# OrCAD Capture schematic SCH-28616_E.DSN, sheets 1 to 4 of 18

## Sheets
1 X-02 IOMUX: title: MCIMX6UL-BB; rev: E; company: Freescale Semiconductor; note: SCH-28616 PDF: SPF-28616; note: 6501 William Cannon Drive West; note: Austin, TX 78735-8598
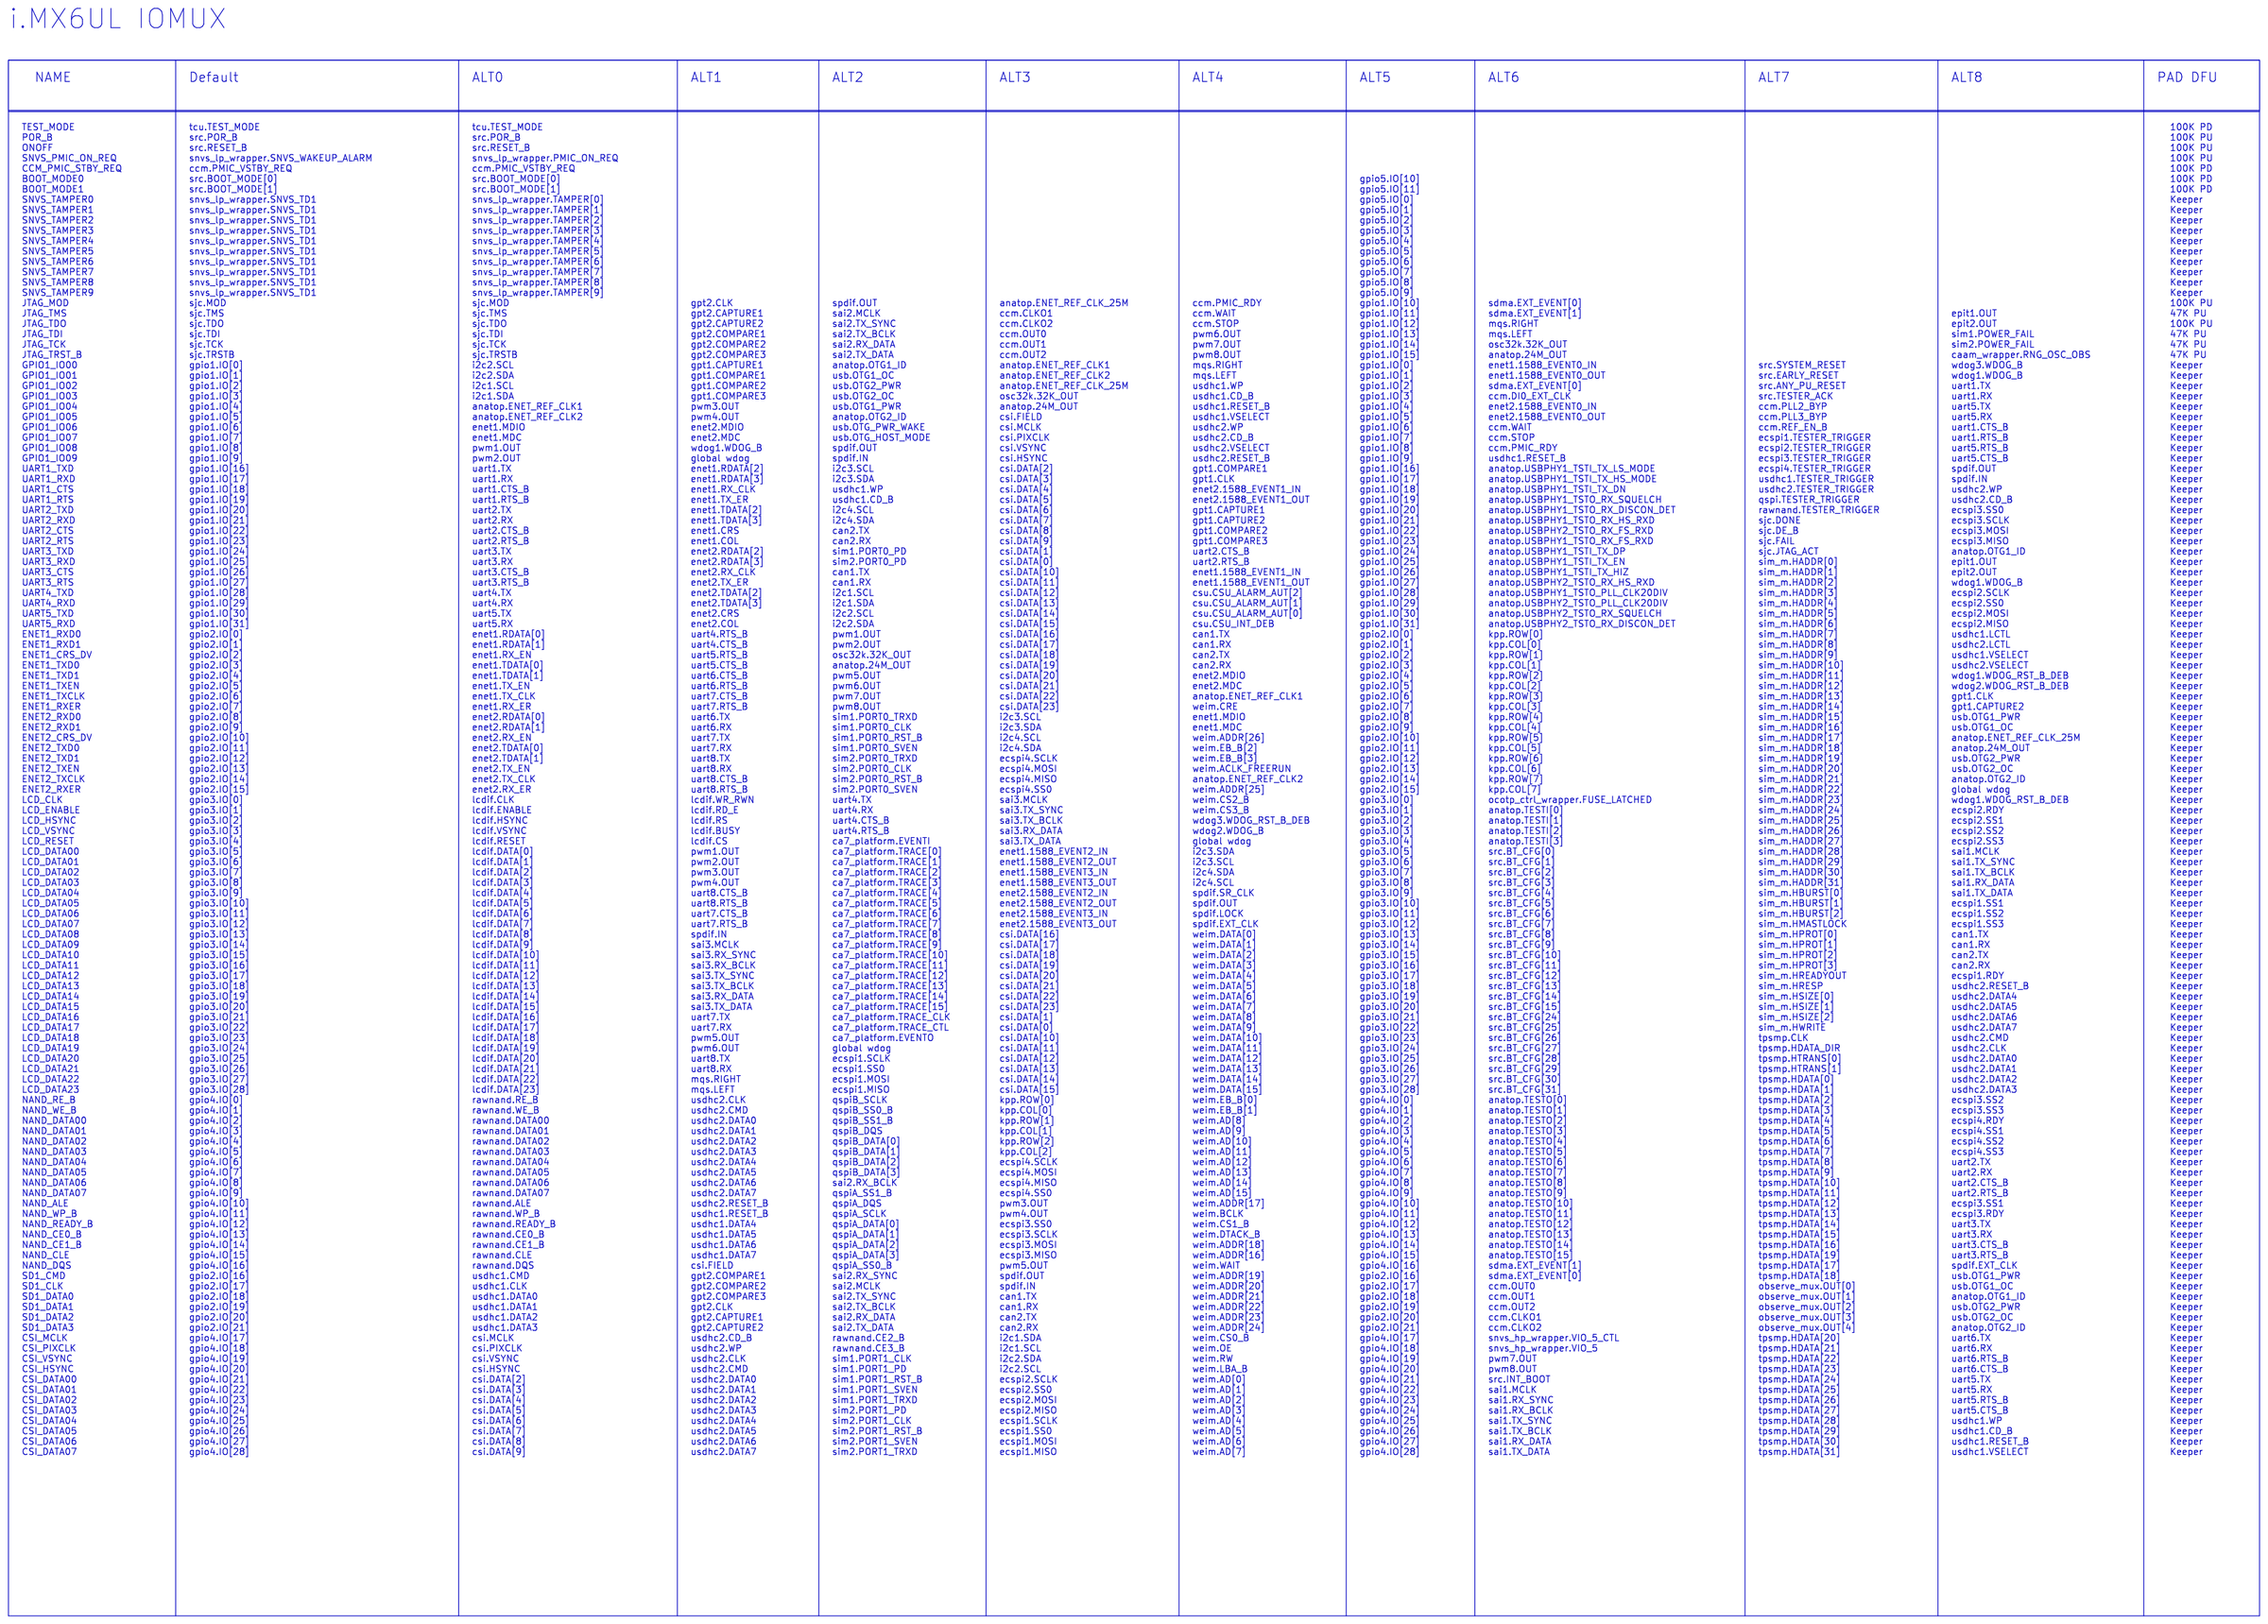
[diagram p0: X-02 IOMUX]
2 X-01 NOTE
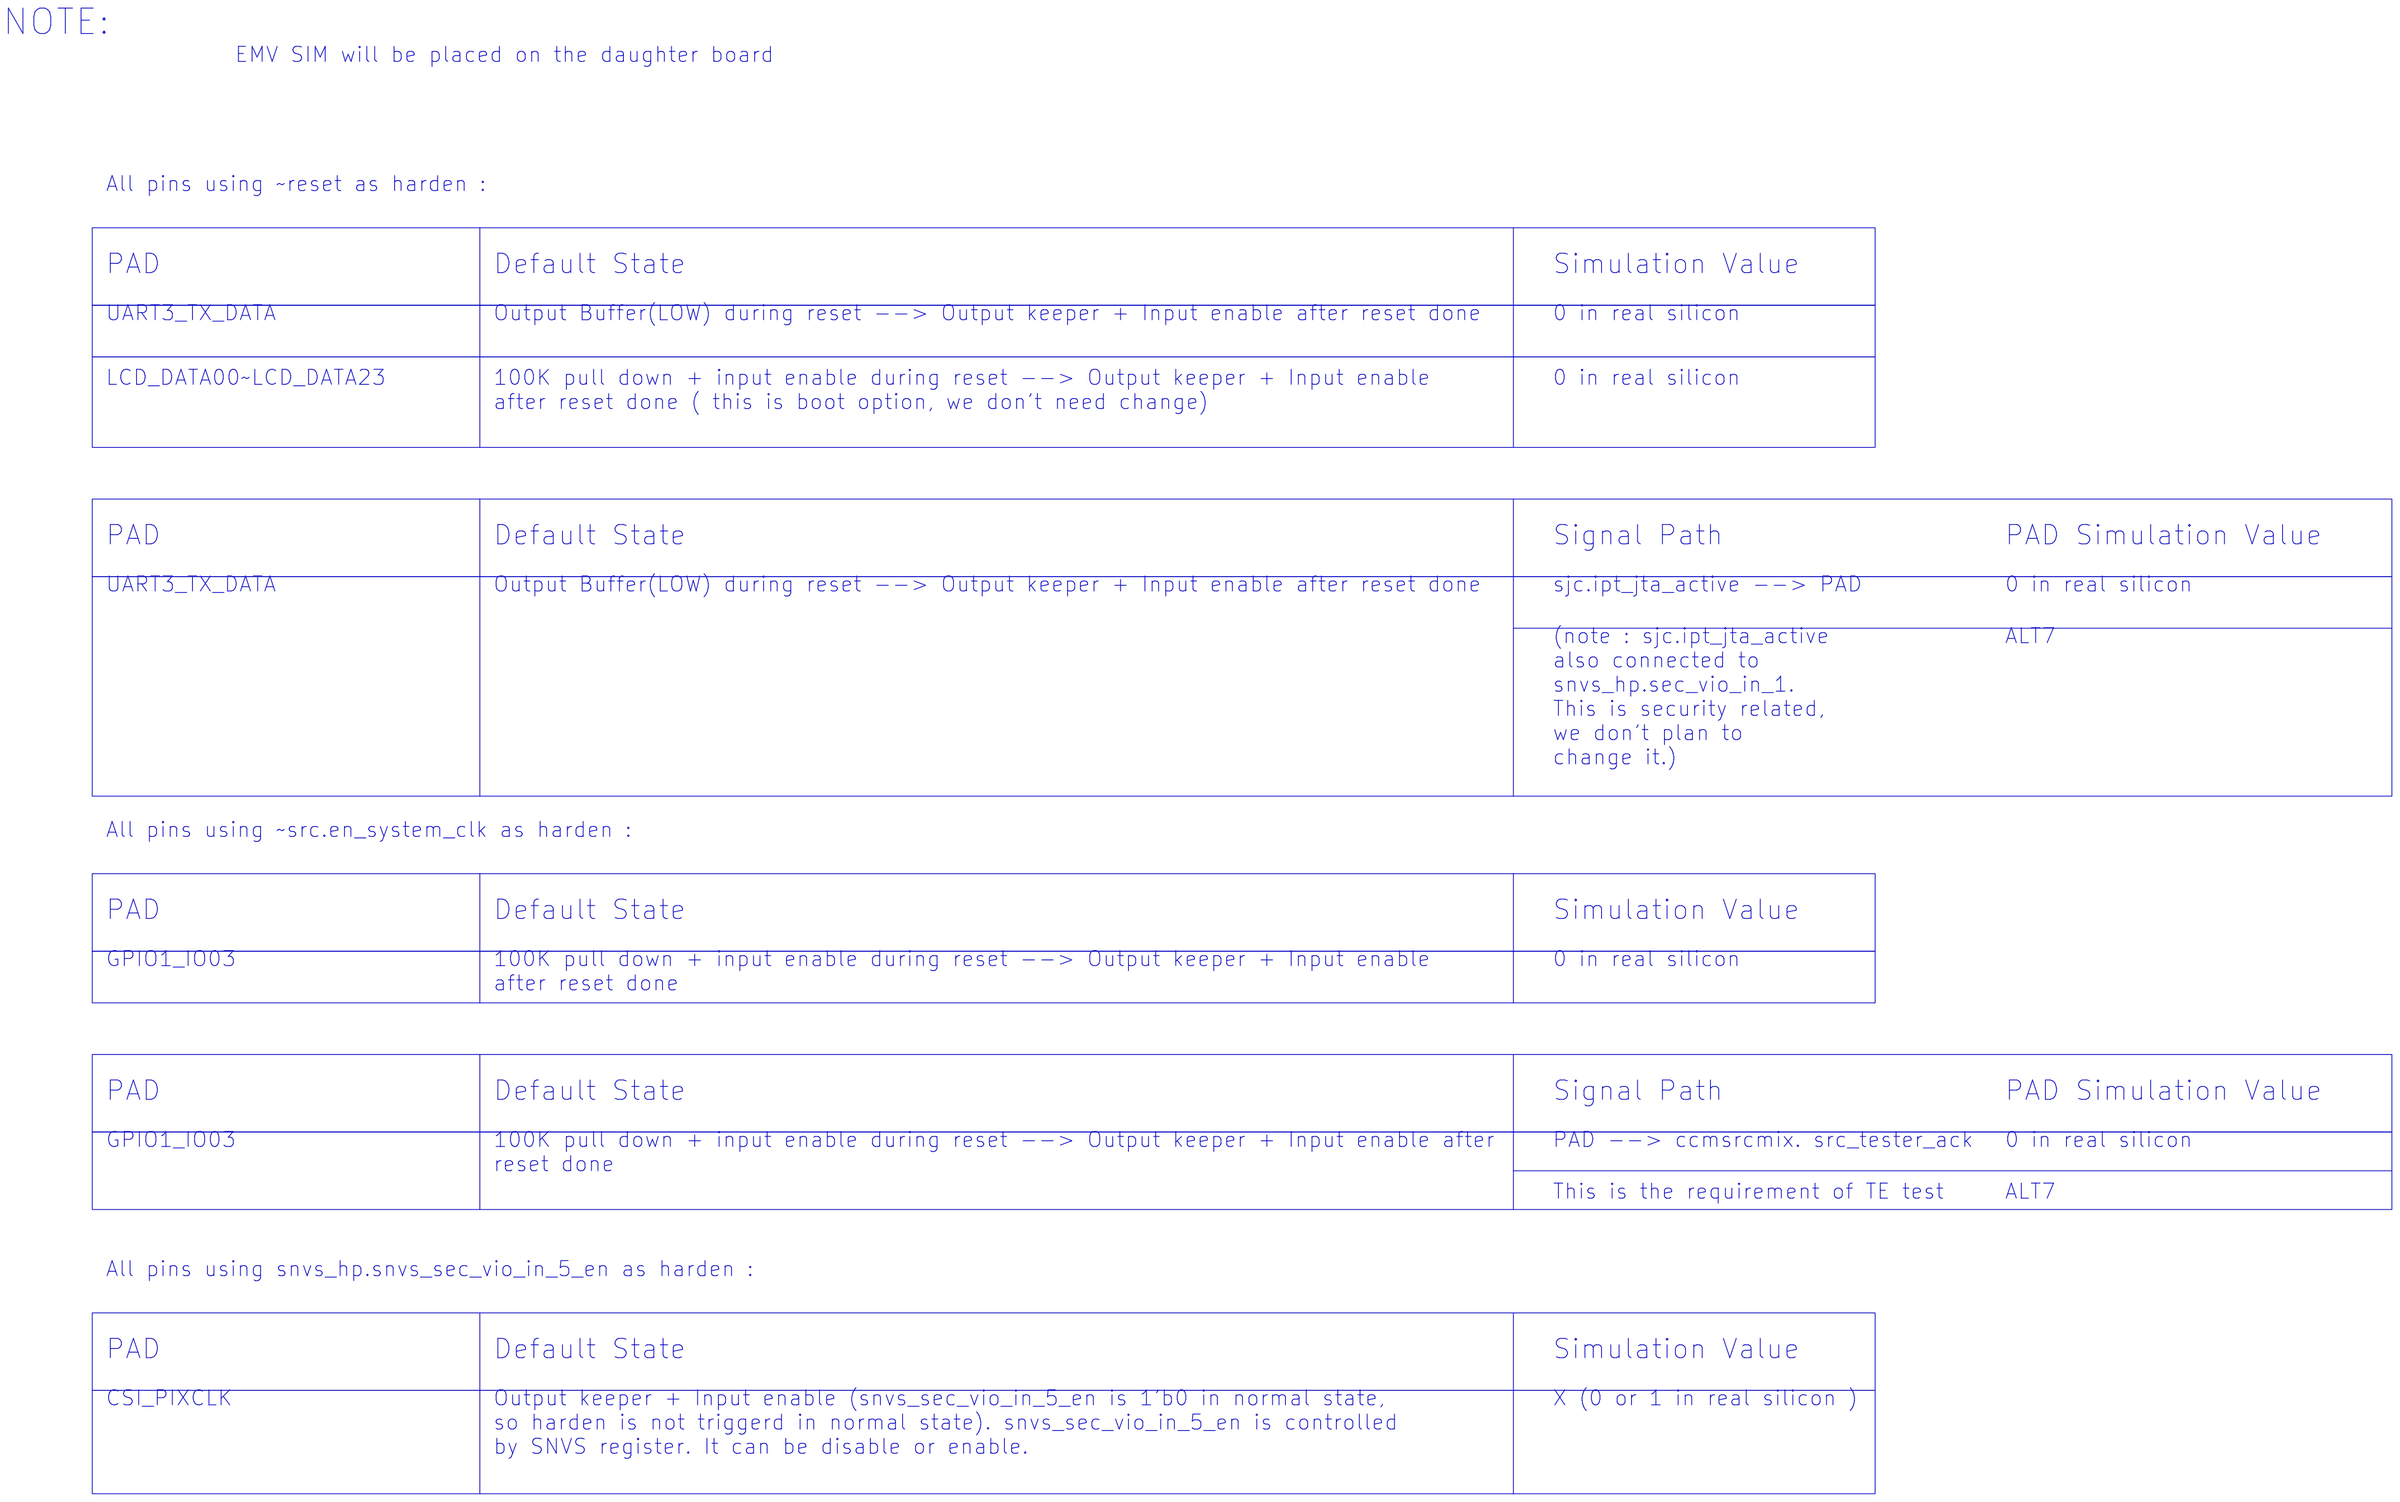
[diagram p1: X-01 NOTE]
3 M-14 SODIMM: size C
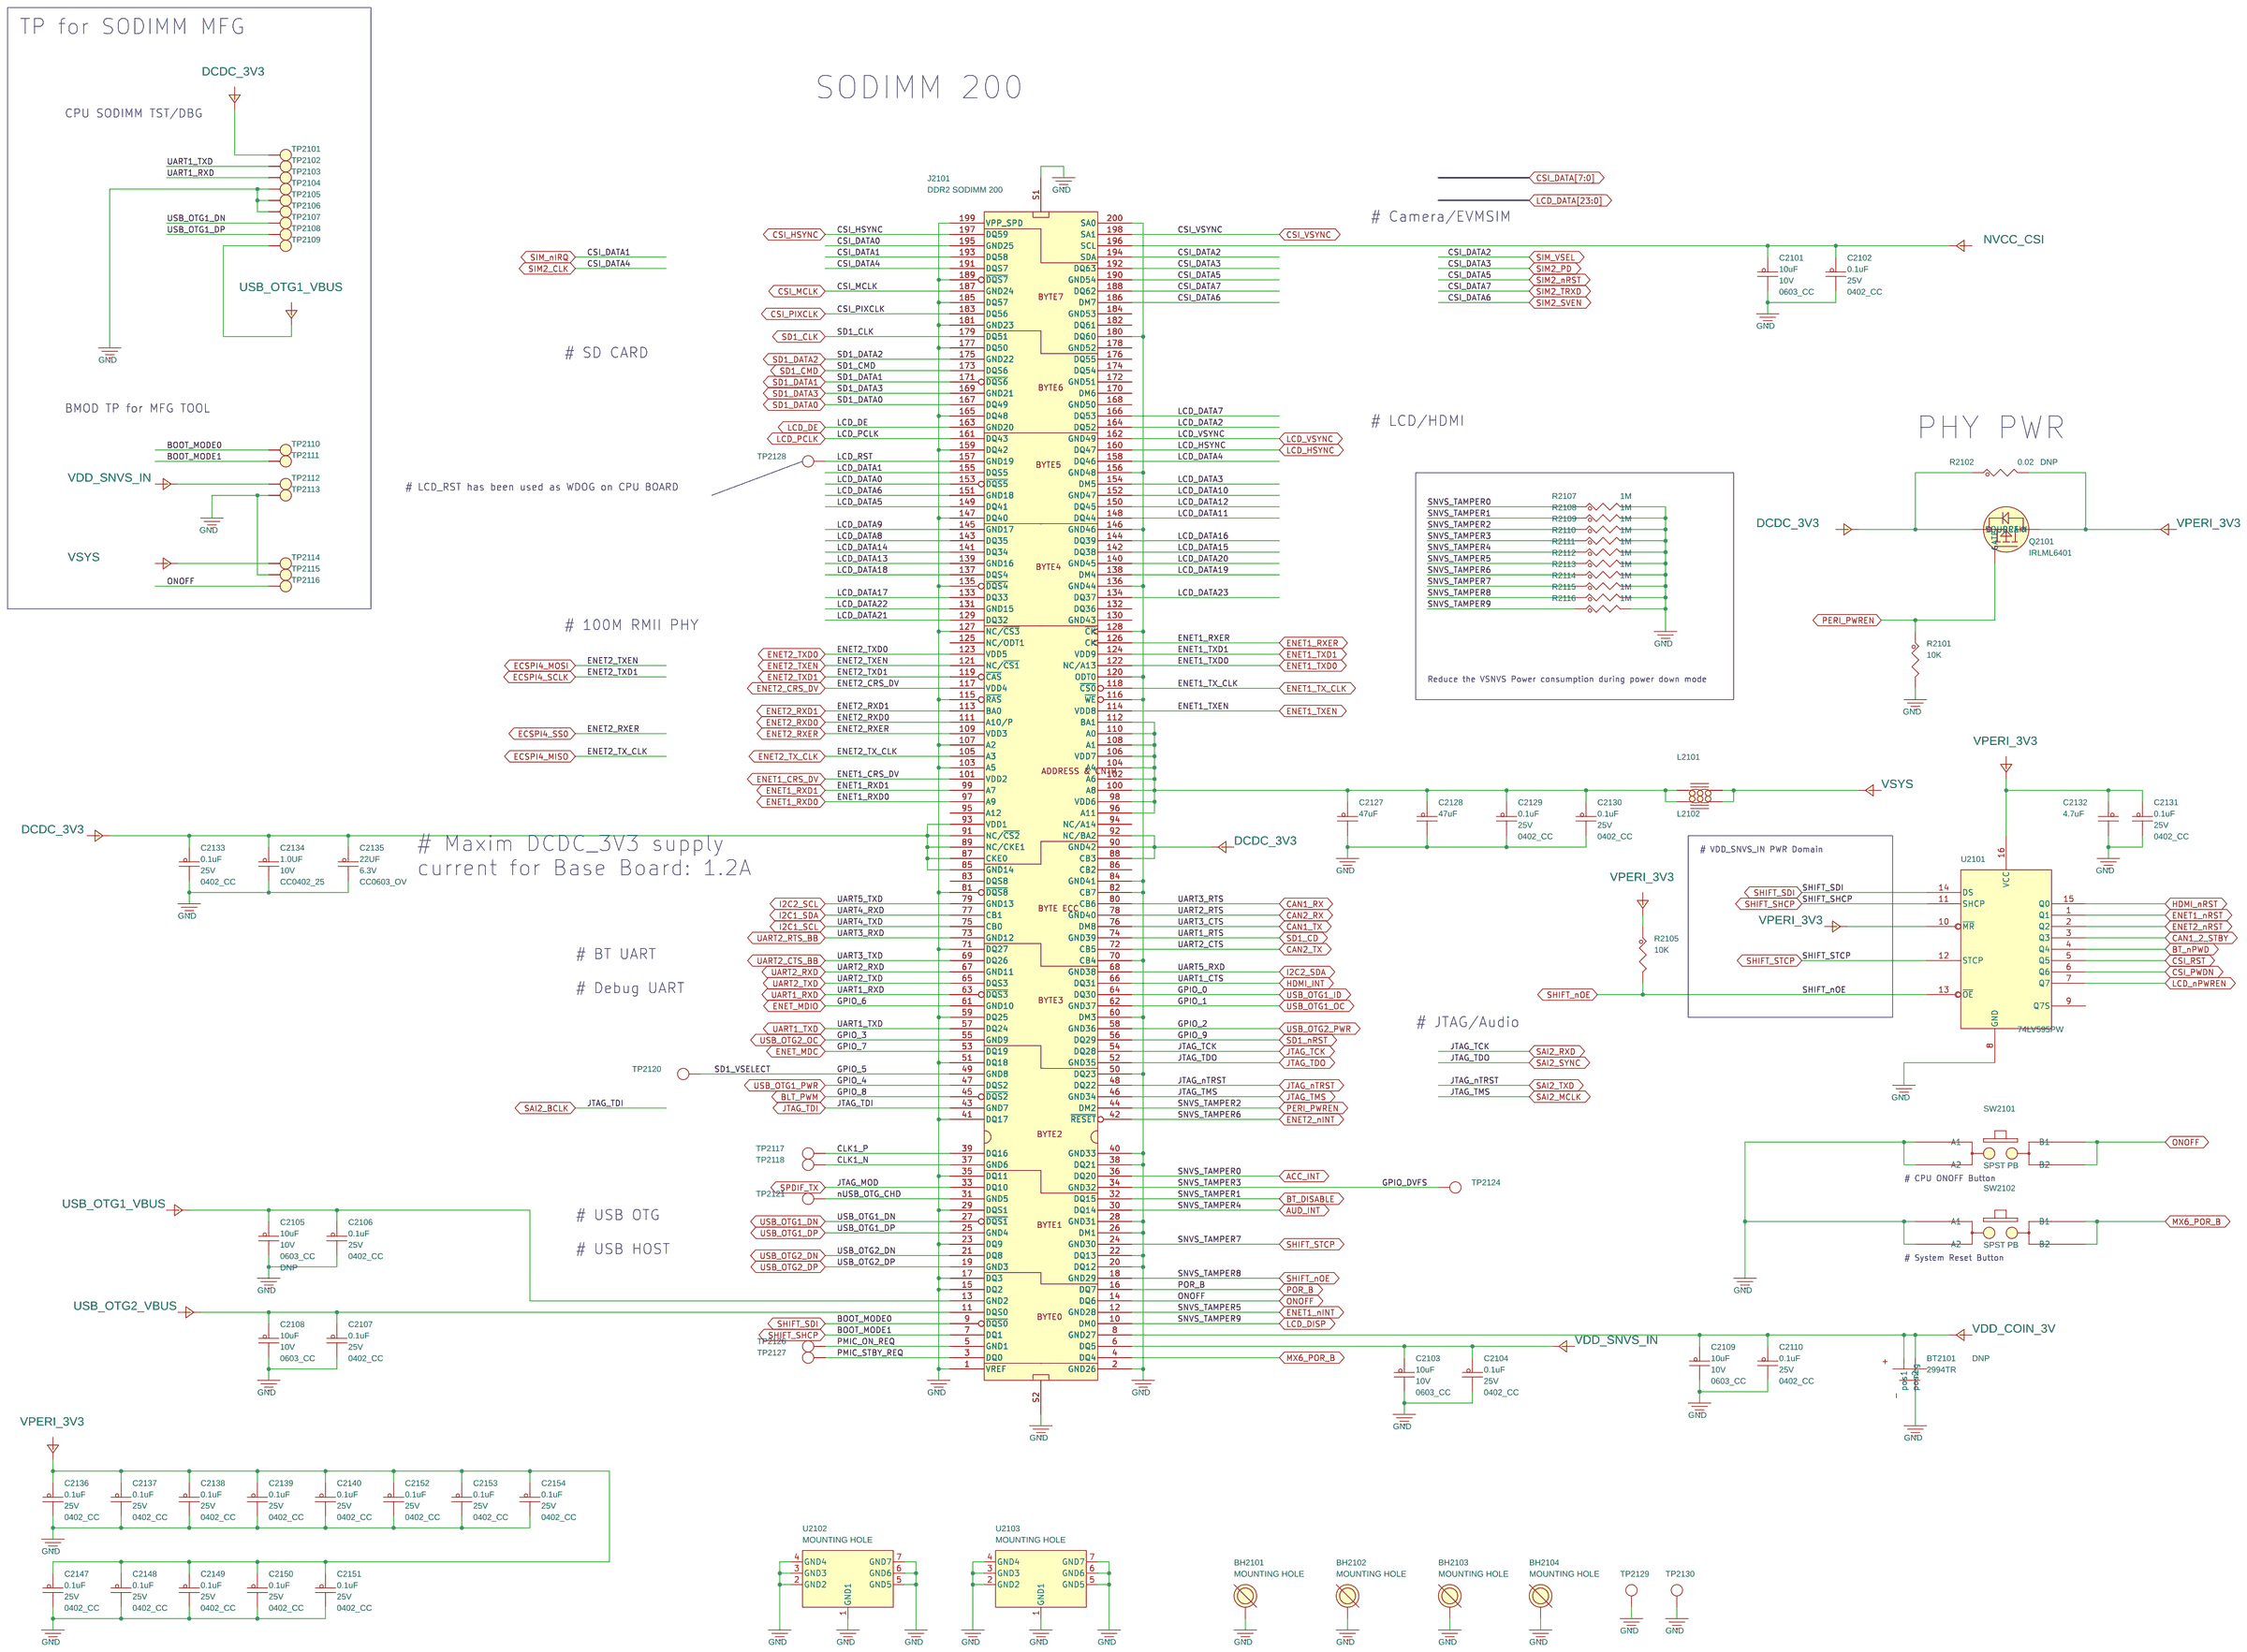
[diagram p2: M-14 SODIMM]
4 M-10 CAMERA: size C
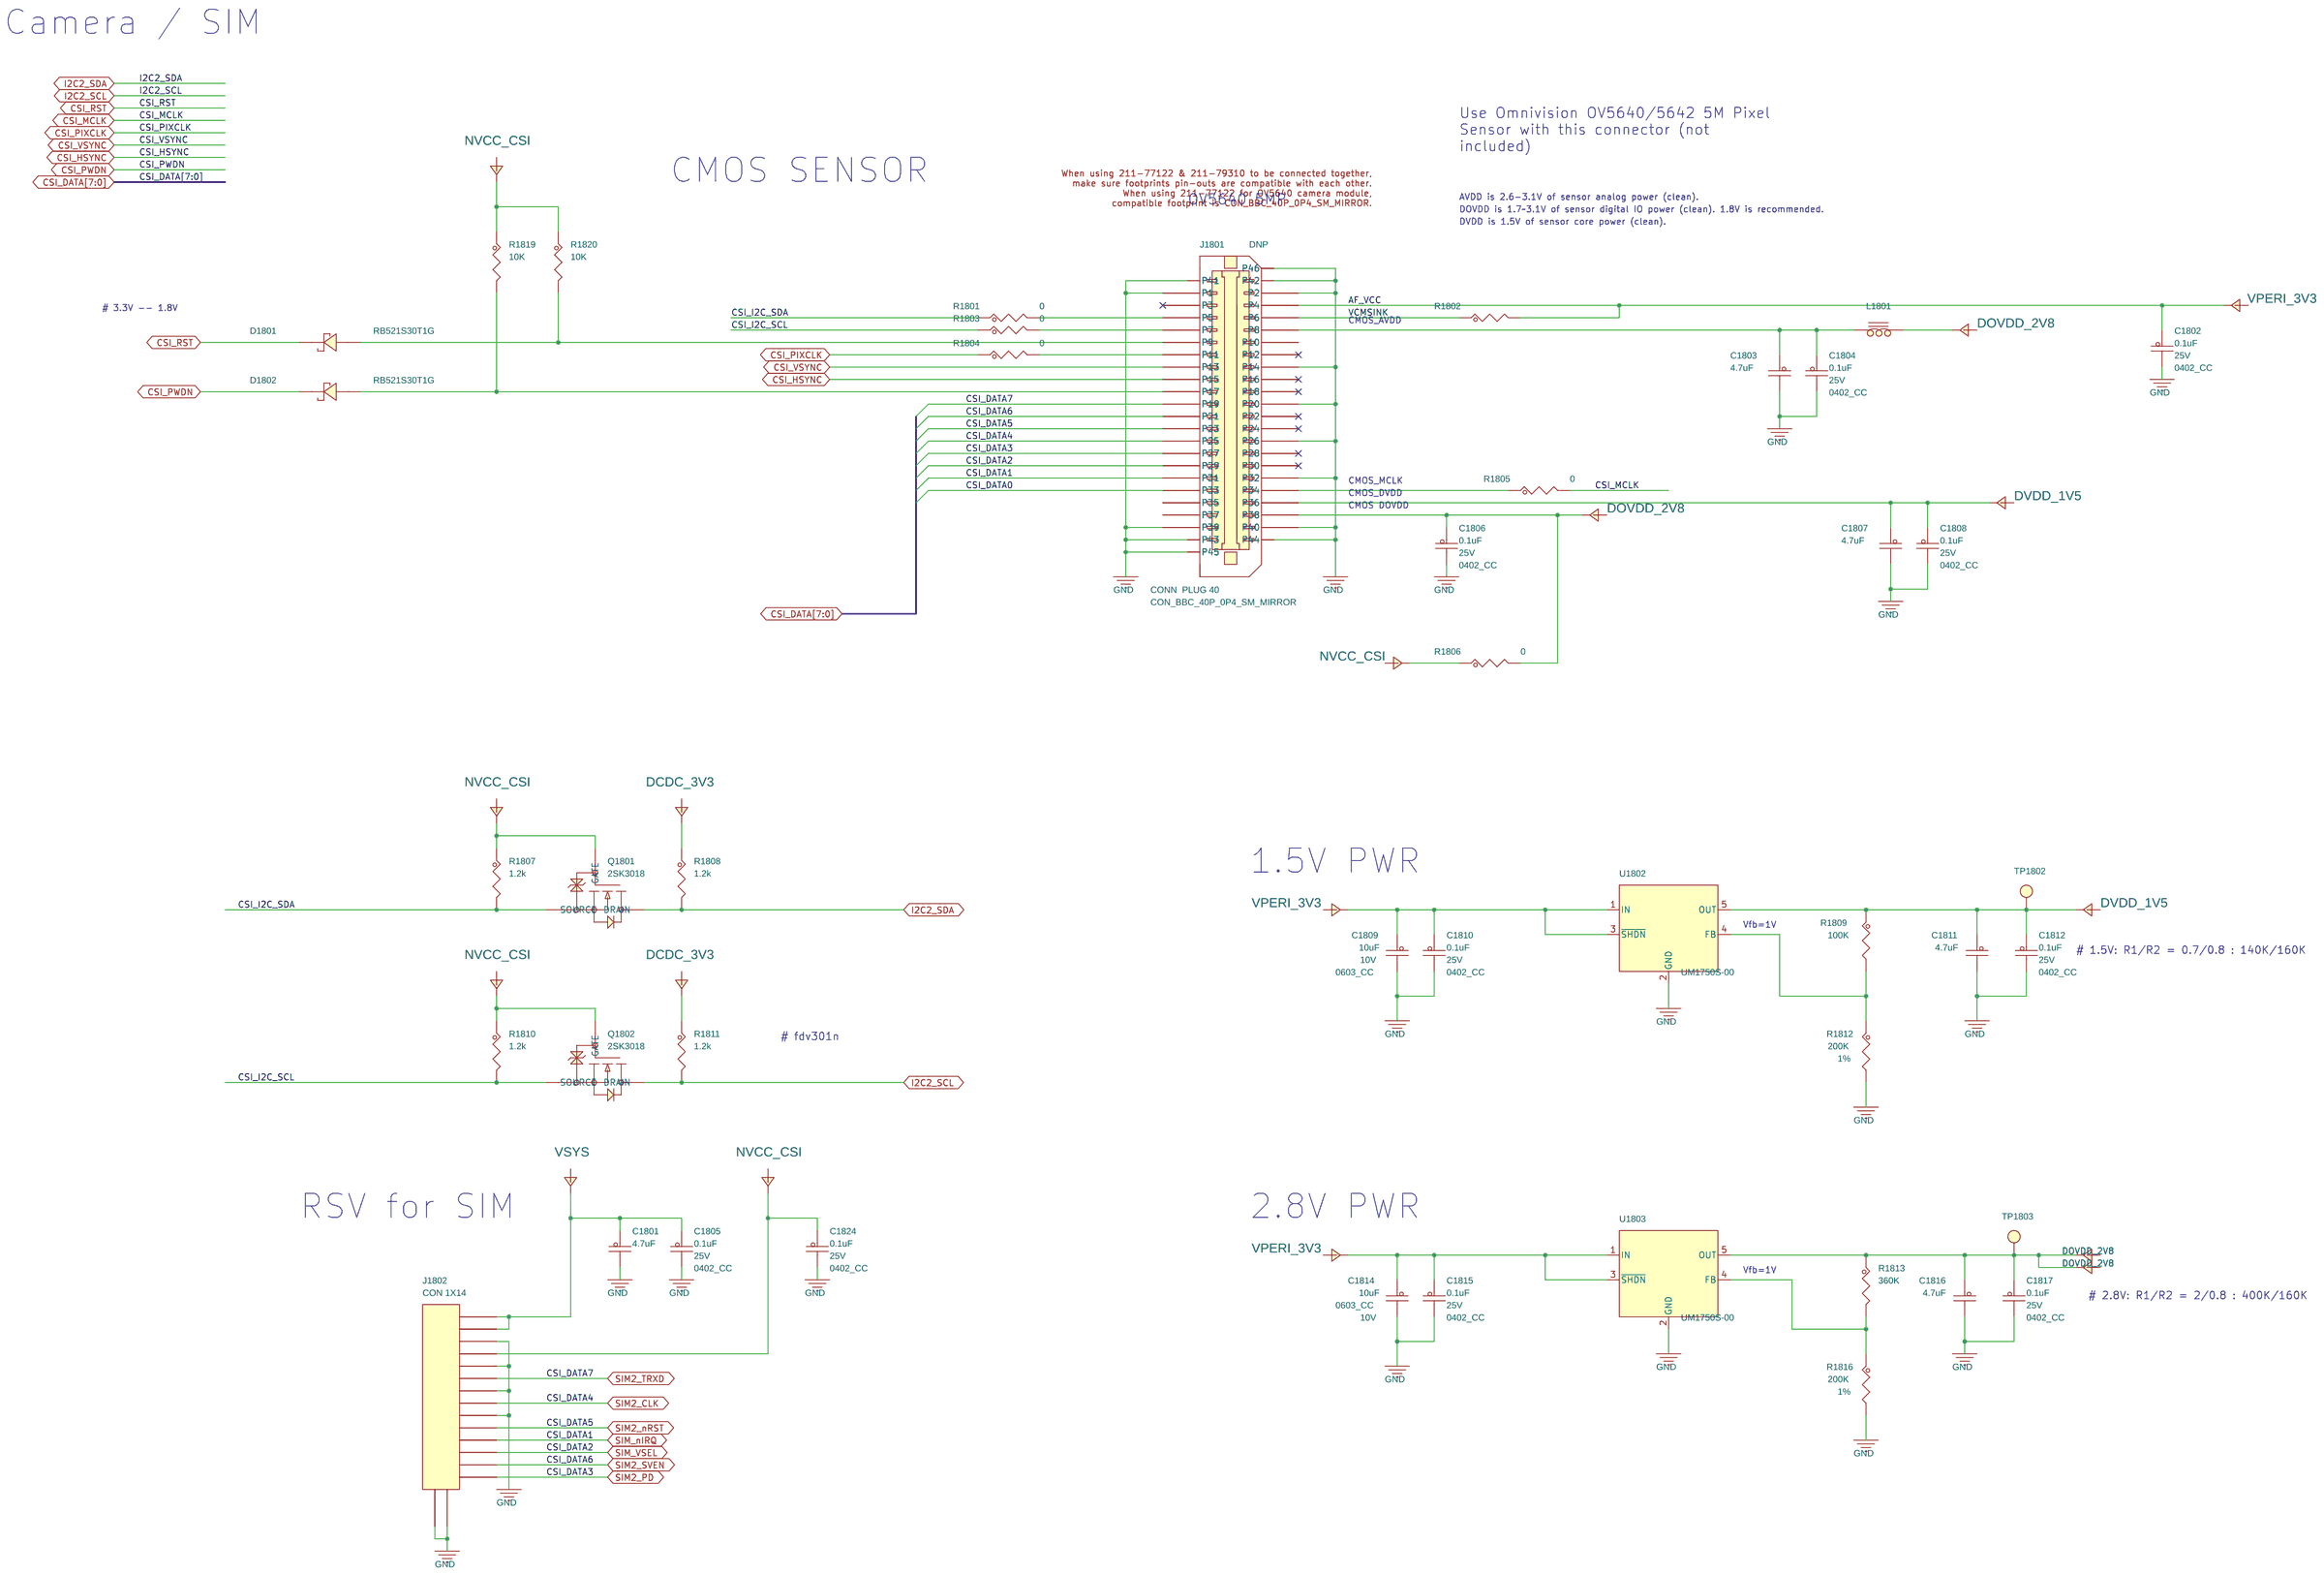
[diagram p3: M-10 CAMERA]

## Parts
sheet M-10 CAMERA
C1801  4.7uF  [cc0402_tol0p15]
C1802  0.1uF  [0402_CC]
C1803  4.7uF  [cc0402_tol0p15]
C1804  0.1uF  [0402_CC]
C1805  0.1uF  [0402_CC]
C1806  0.1uF  [0402_CC]
C1807  4.7uF  [cc0402_tol0p15]
C1808  0.1uF  [0402_CC]
C1809  10uF  [0603_CC]
C1810  0.1uF  [0402_CC]
C1811  4.7uF  [cc0402_tol0p15]
C1812  0.1uF  [0402_CC]
C1814  10uF  [0603_CC]
C1815  0.1uF  [0402_CC]
C1816  4.7uF  [cc0402_tol0p15]
C1817  0.1uF  [0402_CC]
C1824  0.1uF  [0402_CC]
D1801  RB521S30T1G  [sod_523]
D1802  RB521S30T1G  [sod_523]
J1801  CONN  PLUG 40  [CON_BBC_40P_0P4_SM_MIRROR]
J1802  CON 1X14  [con14_fpc_0p5_ra_smt_2sh]
L1801  120OHM  [0603_CC]
Q1801  2SK3018  [SOT323_3]
Q1802  2SK3018  [SOT323_3]
R1801  0  [0402_CC]
R1802  4.70K  [0603_CC]
R1803  0  [0402_CC]
R1804  0  [0402_CC]
R1805  0  [0402_CC]
R1806  0  [0402_CC]
R1807  1.2k  [0402_CC]
R1808  1.2k  [0402_CC]
R1809  100K  [0402_CC]
R1810  1.2k  [0402_CC]
R1811  1.2k  [0402_CC]
R1812  200K  [0402_CC]
R1813  360K  [0402_CC]
R1816  200K  [0402_CC]
R1819  10K  [0402_CC]
R1820  10K  [0402_CC]
TP1802  TP_35MIL  [testpoint_35mil]
TP1803  TP_35MIL  [testpoint_35mil]
U1802  UM1750S-00  [sot23-5_a]
U1803  UM1750S-00  [sot23-5_a]
sheet M-14 SODIMM
BH2101  MOUNTING HOLE  [plated_hole_120_220mil]
BH2102  MOUNTING HOLE  [plated_hole_120_220mil]
BH2103  MOUNTING HOLE  [plated_hole_120_220mil]
BH2104  MOUNTING HOLE  [plated_hole_120_220mil]
BT2101  2994TR  [skt_batt_4x8]
C2101  10uF  [0603_CC]
C2102  0.1uF  [0402_CC]
C2103  10uF  [0603_CC]
C2104  0.1uF  [0402_CC]
C2105  10uF  [0603_CC]
C2106  0.1uF  [0402_CC]
C2107  0.1uF  [0402_CC]
C2108  10uF  [0603_CC]
C2109  10uF  [0603_CC]
C2110  0.1uF  [0402_CC]
C2127  47uF  [0805_CC]
C2128  47uF  [0805_CC]
C2129  0.1uF  [0402_CC]
C2130  0.1uF  [0402_CC]
C2131  0.1uF  [0402_CC]
C2132  4.7uF  [cc0402_tol0p15]
C2133  0.1uF  [0402_CC]
C2134  1.0UF  [CC0402_25]
C2135  22UF  [CC0603_OV]
C2136  0.1uF  [0402_CC]
C2137  0.1uF  [0402_CC]
C2138  0.1uF  [0402_CC]
C2139  0.1uF  [0402_CC]
C2140  0.1uF  [0402_CC]
C2147  0.1uF  [0402_CC]
C2148  0.1uF  [0402_CC]
C2149  0.1uF  [0402_CC]
C2150  0.1uF  [0402_CC]
C2151  0.1uF  [0402_CC]
C2152  0.1uF  [0402_CC]
C2153  0.1uF  [0402_CC]
C2154  0.1uF  [0402_CC]
J2101  DDR2 SODIMM 200  [sodimm_200_std_0p6_sm_wmp]
L2101  120OHM  [0603_CC]
L2102  120OHM  [0603_CC]
Q2101  IRLML6401  [sot-23]
R2101  10K  [0402_CC]
R2102  0.02  [0805_CC]
R2105  10K  [0402_CC]
R2107  1M  [0402_CC]
R2108  1M  [0402_CC]
R2109  1M  [0402_CC]
R2110  1M  [0402_CC]
R2111  1M  [0402_CC]
R2112  1M  [0402_CC]
R2113  1M  [0402_CC]
R2114  1M  [0402_CC]
R2115  1M  [0402_CC]
R2116  1M  [0402_CC]
SW2101  SPST PB  [SW4_PB_ESW_SM_P177]
SW2102  SPST PB  [SW4_PB_ESW_SM_P177]
TP2101  TP_35MIL  [testpoint_35mil]
TP2102  TP_35MIL  [testpoint_35mil]
TP2103  TP_35MIL  [testpoint_35mil]
TP2104  TP_35MIL  [testpoint_35mil]
TP2105  TP_35MIL  [testpoint_35mil]
TP2106  TP_35MIL  [testpoint_35mil]
TP2107  TP_35MIL  [testpoint_35mil]
TP2108  TP_35MIL  [testpoint_35mil]
TP2109  TP_35MIL  [testpoint_35mil]
TP2110  TP_35MIL  [testpoint_35mil]
TP2111  TP_35MIL  [testpoint_35mil]
TP2112  TP_35MIL  [testpoint_35mil]
TP2113  TP_35MIL  [testpoint_35mil]
TP2114  TP_35MIL  [testpoint_35mil]
TP2115  TP_35MIL  [testpoint_35mil]
TP2116  TP_35MIL  [testpoint_35mil]
TP2117  TPAD_020  [tpad_020]
TP2118  TPAD_020  [tpad_020]
TP2120  TPAD_020  [tpad_020]
TP2121  TPAD_020  [tpad_020]
TP2124  TPAD_020  [tpad_020]
TP2126  TPAD_020  [tpad_020]
TP2127  TPAD_020  [tpad_020]
TP2128  TPAD_020  [tpad_020]
TP2129  TESTLOOP  [TEST_PIN_TP107]
TP2130  TESTLOOP  [TEST_PIN_TP107]
U2101  74LV595PW  [TSSOP16]
U2102  MOUNTING HOLE  [mh315-158t_6p]
U2103  MOUNTING HOLE  [mh315-158t_6p]

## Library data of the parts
C1801 C1803 C1807 C1811 C1816 C2132 = CAP_NP: CAP CER 4.7UF 6.3V 20% X5R 0402; AGILE_PN: 150-78463; CAD_APPROVED: Yes; FPLIST: CC0402_25,CC0402_HD,0402_CC; HEIGHT: 0.65MM; MFG_NAME01: TDK; MFG_PN01: C1005X5R0J475M; ROHS: Yes; Rated Voltage: 6.3V; Temp Range: -55C to +85C; Tolerance: 20%; VOLTAGE: 6.3V; voltage rating: 6.3V
C1802 C1804-C1806 C1808 C1810 C1812 C1815 C1817 C1824 C2102 C2104 C2106 C2107 C2110 C2129-C2131 C2133 C2136-C2140 C2147-C2154 = CAP_NP: CAP CER 0.1UF 25V 10% X5R 0402; AGILE_PN: 150-78633; CAD_APPROVED: Yes; FPLIST: CC0402_25,CC0402_HD,0402_CC; HEIGHT: 0.55MM; MFG_NAME01: YAGEO AMERICA; MFG_PN01: CC0402KRX5R8BB104; Package Size: 0402; ROHS: Yes; Rated Voltage: 25V; Temp Range: -55C to +85C; Tolerance: 10%; VOLTAGE: 25V
C1809 C1814 C2101 C2103 C2108 C2109 = CAP_NP: CAP CER 10UF 10V 20% X5R 0603; AGILE_PN: 150-78609; CAD_APPROVED: Yes; FPLIST: CC0603_OV,CC0603,0603_CC; HEIGHT: 1.016MM; MFG_NAME01: TAIYO YUDEN; MFG_PN01: LMK107BJ106MALTD; Package Size: 0603; Package Type: Paper Tape; ROHS: Yes; Rated Voltage: 10V; Temp Range: -55C to +85C; Tolerance: 20%; VOLTAGE: 10V
D1801 D1802 = DIODE_SCHTKY: DIODE SCH 200MA 30V AEC-Q101 SOD-523; 3D_Mechanical_Footprint_File: http://fcl.am.freescale.net/ALLEGRO/step/sod_523.STEP; AGILE_PN: 480-78501; CAD_APPROVED: Yes; HEIGHT: 0.7MM; MFG_NAME01: ON SEMICONDUCTOR; ROHS: Yes; Rated Voltage: 30V
J1801 = FX12B-40P: CON 2X20 PLUG SHLD SMT 0.4MM SP 53H AU; 3D_Mechanical_Footprint_File: http://fcl.am.freescale.net/ALLEGRO/step/CON_BBC_40P_0P4_SM_MIRROR.step; AGILE_PN: 211-77122; ASSY_OPT: DNP; CAD_APPROVED: Yes; FPLIST: CON_BBC_40P_0P4_SM,CON_BBC_40P_0P4_SM_MIRROR; HEIGHT: 1.64MM; MFG_NAME01: HIROSE; MFG_PN01: FX12B-40P-0.4SV; ROHS: Yes
J1802 = CON1X14_2SH: CON 1X14 FPC/FFC RA SMT 0.5MM SP 87H SN/AU; AGILE_PN: TMP-WF-24138; CAD_APPROVED: Yes; FPLIST: con14_fpc_0p5_ra_smt,con14_fpc_0p5_ra_smt_2sh; HEIGHT: 2.2MM; MFG_NAME01: SHENZHEN ATOM TECHNOLOGY CO.,LTD; MFG_PN01: FPC05014-08100; PRE_APN: 211-79711; ROHS: Yes
L1801 L2101 L2102 = BEAD_0: IND FER BEAD 120OHM@100MHZ 2A 25% 0603; AGILE_PN: 180-30008; CAD_APPROVED: Yes; FPLIST: IND_0603,0603_CC; HEIGHT: 0.95MM; MFG_NAME01: MURATA; MFG_PN01: BLM18PG121SH1; PART_TYPE: FERRITE; ROHS: Yes; Tolerance: 25%
Q1801 Q1802 = 2SK3018: TRANS MOSFET N-CH 30V .1A SOT-323; AGILE_PN: 480-75317; CAD_APPROVED: Yes; HEIGHT: 0.9MM; MFG_NAME01: ROHM; MFG_PN01: 2SK3018T106; ROHS: Yes
R1801 R1803-R1806 = RES: RES MF ZERO OHM 1/16W 5% 0402; AGILE_PN: 470-75394; CAD_APPROVED: Yes; FPLIST: RC0402_25,RC0402_HD,RC0402_X2,0402_CC; HEIGHT: 0.45 MM; MFG_NAME01: YAGEO AMERICA; MFG_PN01: RC0402JR-070RL; ROHS: Yes; Tolerance: 5%
R1802 = RES: RES MF 4.70K 1/10W 1% 0603; AGILE_PN: 470-75430; CAD_APPROVED: Yes; FPLIST: RC0603_OV,RC0603,0603_CC; HEIGHT: 0.55 MM; MFG_NAME01: BOURNS; MFG_PN01: CR0603-FX-4701ELF; ROHS: Yes; TOL: 1%; Tolerance: 1%
R1807 R1808 R1810 R1811 = RES: RES MF 1.2k 1/16W 1% AEC-Q200 0402; AGILE_PN: 470-82619; CAD_APPROVED: Yes; FPLIST: RC0402_25,RC0402_HD,0402_CC; HEIGHT: 0.4MM; MFG_NAME01: VISHAY INTERTECHNOLOGY; MFG_PN01: CRCW04021K20FKED; Package Size: 0402 [1005 Metric]; Package Type: Surface Mount; ROHS: Yes; Temp Range: -55°C to 155°C; Tolerance: 1%
R1809 = RES: RES MF 100K 1/16W 1% 0402; AGILE_PN: 470-76240; CAD_APPROVED: Yes; FPLIST: RC0402_25,RC0402_HD,0402_CC; HEIGHT: 0.4MM; MFG_NAME01: VISHAY INTERTECHNOLOGY; MFG_PN01: CRCW0402100KFKEDC; ROHS: Yes; Tolerance: 1%
R1812 R1816 = RES: RES MF 200K 1/10W 1% AEC-Q200 0402; AGILE_PN: 470-31093; CAD_APPROVED: Yes; FPLIST: RC0402_25,RC0402_HD,0402_CC; HEIGHT: 0.40 MM; MFG_NAME01: KOA SPEER; MFG_PN01: RK73H1ETTP2003F; ROHS: Yes; Temp Range: -55C to +155C; Temp_Range: -55C to +155C; Tolerance: 1%
R1813 = RES: RES MF 360K  1/10W 1% AEC-Q200 0402; AGILE_PN: 470-31122; CAD_APPROVED: Yes; FPLIST: RC0402_25,RC0402_HD,0402_CC; HEIGHT: 0.40 MM; MFG_NAME01: KOA SPEER; MFG_PN01: RK73H1ETTP3603F; ROHS: Yes; Temp Range: -55C to +155C; Temp_Range: -55C to +155C; Tolerance: 1%
R1819 R1820 R2101 R2105 = RES: RES MF 10K 1/16W 5% 0402; AGILE_PN: 470-75557; CAD_APPROVED: Yes; FPLIST: RC0402_25,RC0402_HD,0402_CC; HEIGHT: 0.4 MM; MFG_NAME01: VISHAY INTERTECHNOLOGY; MFG_PN01: CRCW040210K0JNED; ROHS: Yes; Tolerance: 5%
TP1802 TP1803 TP2101-TP2116 = T_POINT_R: TEST POINT PAD .035 SMT, no part to order; AGILE_PN: 510-75618; CAD_APPROVED: Yes; HEIGHT: 0.1MM; ROHS: Yes
U1802 U1803 = UM1750S-00_5P: IC VREG LDO ADJ 1-5V 350mA 2.5-6V SOT23-5; 3D_Mechanical_Footprint_File: http://fcl.am.freescale.net/ALLEGRO/step/sot23-5_a.STEP; AGILE_PN: 315-80554; CAD_APPROVED: Yes; HEIGHT: 1.25MM; MFG_NAME01: UNION SEMICONDUCTOR, INC; ROHS: Yes; VOLTAGE: 2.5-6V
BH2101-BH2104 = MOUNT_HOLE: MOUNTING HOLE DRILL 120mil PAD 220mil PLATED TH NO PART TO ORDER; AGILE_PN: 280-76315; CAD_APPROVED: Yes; HEIGHT: 0.1MM; MFG_NAME01: N/A; MFG_PN01: N/A; ROHS: Yes
BT2101 = BATTERY_SKT_3V: BATTERY RETAINER COIN CELL 4.8MM SMT; 3D_Mechanical_Footprint_File: http://fcl.am.freescale.net/ALLEGRO/step/ skt_batt_4x8.step; AGILE_PN: 801-76071; ASSY_OPT: DNP; CAD_APPROVED: Yes; HEIGHT: 1.7MM; MFG_NAME01: KEYSTONE ELECTRONICS; ROHS: Yes
C2105 = CAP_NP: CAP CER 10UF 10V 20% X5R 0603; AGILE_PN: 150-78609; ASSY_OPT: DNP; CAD_APPROVED: Yes; FPLIST: CC0603_OV,CC0603,0603_CC; HEIGHT: 1.016MM; MFG_NAME01: TAIYO YUDEN; MFG_PN01: LMK107BJ106MALTD; Package Size: 0603; Package Type: Paper Tape; ROHS: Yes; Rated Voltage: 10V; Temp Range: -55C to +85C; Tolerance: 20%; VOLTAGE: 10V
C2127 C2128 = CAP_NP: CAP CER 47uF 10V 20% X5R 0805; AGILE_PN: 150-78979; CAD_APPROVED: Yes; FPLIST: CC0805_OV,CC0805,0805_CC; HEIGHT: 1.45 MM; MFG_NAME01: TDK; MFG_PN01: C2012X5R1A476M125AC; ROHS: Yes; Rated Voltage: 10V; Temp Range: -55C to +85C; Tolerance: 20%; VOLTAGE: 10V
C2134 = CAP_NP: CAP CER 1.0UF 10V 10% X5R 0402; AGILE_PN: 150-75772; CAD_APPROVED: Yes; FPLIST: CC0402_25,CC0402_HD,0402_CC; HEIGHT: 0.6MM; MFG_NAME01: YAGEO AMERICA; MFG_PN01: CC0402KRX5R6BB105; Package Size: 0402; ROHS: Yes; Rated Voltage: 10V; Temp Range: -55C to +85C; Tolerance: 10%; VOLTAGE: 10V
C2135 = CAP_NP: CAP CER 22UF 6.3V 20% X5R 0603; AGILE_PN: 150-78467; CAD_APPROVED: Yes; FPLIST: CC0603_OV,CC0603,0603_CC; HEIGHT: 1MM; MFG_NAME01: SAMSUNG; MFG_PN01: CL10A226MQ8NRNE; Package Size: 0603; ROHS: Yes; Rated Voltage: 6.3V; Temp Range: -55C to +85C; Tolerance: 20%; VOLTAGE: 6.3V; voltage rating: 6.3V
J2101 = SD200_A: CON 200 SODIMM DDR2 1.8V SKT RA SMT 0.6MM SP 323H AU; 3D_Mechanical_Footprint_File: http://fcl.am.freescale.net/ALLEGRO/step/sodimm_200_std_0p6_sm.STEP; AGILE_PN: 211-78042; CAD_APPROVED: Yes; FPLIST: sodimm_200_std_0p6_sm,sodimm_200_std_0p6_sm_wmp; HEIGHT: 8.7MM; MFG_NAME01: TYCO ELECTRONICS; MFG_PN01: 1827341-4; ROHS: Yes
Q2101 = MOSFET_P: TRAN PMOS PWR 12V 4.3A SOT23; AGILE_PN: 480-77718; CAD_APPROVED: Yes; HEIGHT: 1.12MM; MFG_NAME01: INTERNATIONAL RECTIFIER; MFG_PN01: IRLML6401TRPBF; ROHS: Yes
R2102 = RES: RES MF 0.02 OHM 1/4W 1% 0805; AGILE_PN: 470-30324; ASSY_OPT: DNP; CAD_APPROVED: Yes; FPLIST: RC0805_OV,RC0805,0805_CC; HEIGHT: 0.65MM; MFG_NAME01: KOA SPEER; MFG_PN01: UR73D2ATTD20L0F; ROHS: Yes; Temp Range: +55°C to +125°C; Temp_Range: +55°C to +125°C; Tolerance: 1%
R2107-R2116 = RES: RES MF 1M 1/16W 1% 0402; AGILE_PN: 470-80575; CAD_APPROVED: Yes; FPLIST: RC0402_25,RC0402_HD,0402_CC; HEIGHT: 0.4MM; MFG_NAME01: BOURNS; MFG_PN01: CR0402-FX-1004GLF; ROHS: Yes; Tolerance: 1%
SW2101 SW2102 = SW_PB_ESW: SW SPST MOM NO PB TACT 50mA 50V SMT; AGILE_PN: 510-77562; CAD_APPROVED: Yes; HEIGHT: 5MM; MFG_NAME01: E SWITCH; MFG_PN01: TL3301AF260QG/TR; ROHS: Yes
TP2117 TP2118 TP2120 TP2121 TP2124 TP2126-TP2128 = TESTLOOP: TEST POINT PAD 0.5MM DIA SMT, NO PART TO ORDER; AGILE_PN: 211-77484; CAD_APPROVED: Yes; HEIGHT: 0.1MM; ROHS: Yes
TP2129 TP2130 = TESTLOOP: TEST POINT PAD SIZE 4.7MM X 3.5MM SN; 3D_Mechanical_Footprint_File: http://fcl.am.freescale.net/ALLEGRO/step/TEST_PIN_TP107.STEP; AGILE_PN: 211-30043; CAD_APPROVED: Yes; HEIGHT: 2.286MM; MFG_NAME01: KEYSTONE ELECTRONICS; MFG_PN01: 5016; ROHS: Yes; Temp Range: -50°C to +146°C
U2101 = 74LV595: IC REG S 8BIT TS 1.0-3.6V TSSOP16; AGILE_PN: 312-79843; CAD_APPROVED: Yes; HEIGHT: 1.1MM; MFG_NAME01: PHILIPS SEMICONDUCTOR; ROHS: Yes; VOLTAGE: 1.0-3.6V
U2102 U2103 = MOUNTING_HOLE_ATX_6P: MOUNTING HOLE DRILL 158 PAD 315 VIAX6(PAD-40 DRILL-20) NO PART TO ORDER; AGILE_PN: 280-76944; CAD_APPROVED: Yes; HEIGHT: 0.127MM; ROHS: Yes

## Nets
AVDD_2V8: C1806.1 C1816.1 C1817.1 J1801.38(P38) L1801.2 R1806.2 R1813.1 TP1803.1(TP) U1803.5(OUT)
DVDD_1V5: C1807.1 C1808.1 C1811.1 C1812.1 J1801.36(P36) R1809.1 TP1802.1(TP) U1802.5(OUT)
GND: BH2101.1 BH2102.1 BH2103.1 BH2104.1 BT2101.3(neg) C1801.2 C1802.2 C1803.2 C1804.2 C1805.2 C1806.2 C1807.2 C1808.2 C1809.2 C1810.2 C1811.2 C1812.2 C1814.2 C1815.2 C1816.2 C1817.2 C1824.2 C2101.2 C2102.2 C2103.2 C2104.2 C2105.2 C2106.2 C2107.2 C2108.2 C2109.2 C2110.2 C2127.2 C2128.2 C2129.2 C2130.2 C2131.2 C2132.2 C2133.2 C2134.2 C2135.2 C2136.2 C2137.2 C2138.2 C2139.2 C2140.2 C2147.2 C2148.2 C2149.2 C2150.2 C2151.2 C2152.2 C2153.2 C2154.2 J1801.1(P1) J1801.2(P2) J1801.14(P14) J1801.20(P20) J1801.26(P26) J1801.32(P32) J1801.39(P39) J1801.40(P40) J1801.41(P41) J1801.42(P42) J1801.43(P43) J1801.44(P44) J1801.45(P45) J1801.46(P46) J1802.3 J1802.5 J1802.7 J1802.9 J1802.S1 J1802.S2 J2101.1(VREF) J2101.2(GND26) J2101.15(DQ2) J2101.17(DQ3) J2101.20(DQ12) J2101.22(DQ13) J2101.23(DQ9) J2101.26(DM1) J2101.28(GND31) J2101.29(DQS1) J2101.35(DQ11) J2101.38(DQ21) J2101.40(GND33) J2101.41(DQ17) J2101.50(DQ23) J2101.51(DQ18) J2101.59(DQ25) J2101.60(DM3) J2101.70(CB4) J2101.71(DQ27) J2101.81(~{DQS8}) J2101.82(CB7) J2101.84(GND41) J2101.103(A5) J2101.107(A2) J2101.115(~{RAS}) J2101.116(~{WE}) J2101.120(ODT0) J2101.127(NC/~{CS3}) J2101.128(~{CK}) J2101.135(~{DQS4}) J2101.136(GND44) J2101.146(GND46) J2101.147(DQ40) J2101.156(GND48) J2101.159(DQ42) J2101.165(DQ48) J2101.177(DQ50) J2101.180(DQ60) J2101.181(GND23) J2101.185(DQ57) J2101.189(~{DQS7}) J2101.199(VPP_SPD) J2101.200(SA0) J2101.S1 J2101.S2 R1812.2 R1816.2 R2101.2 R2107.2 R2108.2 R2109.2 R2110.2 R2111.2 R2112.2 R2113.2 R2114.2 R2115.2 R2116.2 SW2101.1(A1) SW2101.2(A2) SW2102.1(A1) SW2102.2(A2) TP2104.1(TP) TP2105.1(TP) TP2106.1(TP) TP2113.1(TP) TP2115.1(TP) TP2129.1(Pin1) TP2130.1(Pin1) U1802.2(GND) U1803.2(GND) U2101.8(GND) U2102.1(GND1) U2102.2(GND2) U2102.3(GND3) U2102.4(GND4) U2102.5(GND5) U2102.6(GND6) U2102.7(GND7) U2103.1(GND1) U2103.2(GND2) U2103.3(GND3) U2103.4(GND4) U2103.5(GND5) U2103.6(GND6) U2103.7(GND7) ; also on sheet 5 6 7 8 12 13 14 15 16 17 18
GND43: J2101.130(GND43)
GND50: J2101.168(GND50)
GND51: J2101.172(GND51)
GND52: J2101.178(GND52)
GND53: J2101.184(GND53)
VDD_COIN_3V: BT2101.1(pos1) BT2101.2(pos2) C2109.1 C2110.1 J2101.8(GND27)
VDD_SNVS_IN: C2103.1 C2104.1 J2101.6(DQ5) TP2112.1(TP)
ACC_INT: J2101.36(DQ20) R2107.1 ; also on sheet 6
AUD_INT: J2101.30(DQ14) R2111.1 ; also on sheet 5
BLT_PWM: J2101.45(~{DQS2}) ; also on sheet 8
BT_DISABLE: J2101.32(DQ15) R2108.1 ; also on sheet 18
BT_nPWD: U2101.4(Q4) ; also on sheet 18
CAN1_2_STBY: U2101.3(Q3) ; also on sheet 7
CAN1_RX: J2101.80(CB6) ; also on sheet 7
CAN1_TX: J2101.76(DM8) ; also on sheet 7
CAN2_RX: J2101.78(GND40) ; also on sheet 7
CAN2_TX: J2101.72(CB5) ; also on sheet 7
CLK1_N: J2101.37(GND6) TP2118.1(Pin1)
CLK1_P: J2101.39(DQ16) TP2117.1(Pin1)
CSI_DATA0: J1801.33(P33) J2101.195(GND25)
CSI_DATA1: J1801.31(P31) J1802.11 J2101.193(DQ58)
CSI_DATA2: J1801.29(P29) J1802.12 J2101.194(SDA)
CSI_DATA3: J1801.27(P27) J1802.14 J2101.192(DQ63)
CSI_DATA4: J1801.25(P25) J1802.8 J2101.191(DQS7)
CSI_DATA5: J1801.23(P23) J1802.10 J2101.190(GND54)
CSI_DATA6: J1801.21(P21) J1802.13 J2101.186(DM7)
CSI_DATA7: J1801.19(P19) J1802.6 J2101.188(DQ62)
CSI_HSYNC: J1801.15(P15) J2101.197(DQ59)
CSI_I2C_SCL: Q1802.1(SOURCE) R1803.1 R1810.2
CSI_I2C_SDA: Q1801.1(SOURCE) R1801.1 R1807.2
CSI_MCLK: J2101.187(GND24) R1805.2
CSI_PIXCLK: J2101.183(DQ56) R1804.1
CSI_PWDN: D1802.C U2101.6(Q6)
CSI_RST: D1801.C U2101.5(Q5)
CSI_VSYNC: J1801.13(P13) J2101.198(SA1)
DCDC_3V3: C2133.1 C2134.1 C2135.1 J2101.85(GND14) J2101.87(CKE0) J2101.88(CB3) J2101.89(NC/CKE1) J2101.90(GND42) J2101.91(NC/~{CS2}) J2101.92(NC/BA2) J2101.93(VDD1) Q2101.2(SOURCE) R1808.1 R1811.1 R2102.1 TP2101.1(TP) ; also on sheet 8 12 16 17 18
ECSPI4_MISO: J2101.105(A3) ; also on sheet 8 14 18
ECSPI4_MOSI: J2101.121(NC/~{CS1}) ; also on sheet 8 14 18
ECSPI4_SCLK: J2101.119(~{CAS}) ; also on sheet 8 14 18
ECSPI4_SS0: J2101.109(VDD3) ; also on sheet 8 14 18
ENET1_CRS_DV: J2101.101(VDD2) ; also on sheet 13
ENET1_nINT: J2101.12(GND28) R2112.1 ; also on sheet 13
ENET1_nRST: U2101.1(Q1) U2101.2(Q2) ; also on sheet 13 14
ENET1_RXD0: J2101.97(A9) ; also on sheet 13
ENET1_RXD1: J2101.99(A7) ; also on sheet 13
ENET1_RXER: J2101.126(CK) ; also on sheet 13
ENET1_TX_CLK: J2101.118(~{CS0}) ; also on sheet 13
ENET1_TXD0: J2101.122(NC/A13) ; also on sheet 13
ENET1_TXD1: J2101.124(VDD9) ; also on sheet 13
ENET1_TXEN: J2101.114(VDD8) ; also on sheet 13
ENET2_CRS_DV: J2101.117(VDD4) ; also on sheet 14
ENET2_nINT: J2101.42(~{RESET}) R2113.1 ; also on sheet 14
ENET2_RXD0: J2101.111(A10/P) ; also on sheet 14
ENET2_RXD1: J2101.113(BA0) ; also on sheet 14
ENET2_TXD0: J2101.123(VDD5) ; also on sheet 14
ENET_MDC: J2101.53(DQ19) ; also on sheet 13 14
ENET_MDIO: J2101.61(GND10) ; also on sheet 13 14
GPIO_5: J2101.49(GND8) TP2120.1(Pin1)
GPIO_DVFS: J2101.34(GND32) R2110.1 TP2124.1(Pin1)
HDMI_INT: J2101.66(DQ31) ; also on sheet 12
HDMI_nRST: U2101.15(Q0) ; also on sheet 12
I2C1_SCL: J2101.75(CB0) ; also on sheet 6
I2C1_SDA: J2101.77(CB1) ; also on sheet 6
I2C2_SCL: J2101.79(GND13) Q1802.3(DRAIN) R1811.2 ; also on sheet 5 8 12 18
I2C2_SDA: J2101.68(GND38) Q1801.3(DRAIN) R1808.2 ; also on sheet 5 8 12 18
JTAG_nTRST: J2101.48(DQ22) ; also on sheet 5 16
JTAG_TCK: J2101.54(DQ28) ; also on sheet 5 16
JTAG_TDI: J2101.43(GND7) ; also on sheet 5 16
JTAG_TDO: J2101.52(GND35) ; also on sheet 5 16
JTAG_TMS: J2101.46(GND34) ; also on sheet 5 16
LCD_DATA0: J2101.153(~{DQS5}) ; also on sheet 8 12
LCD_DATA1: J2101.155(DQS5) ; also on sheet 8 12
LCD_DATA2: J2101.164(DQ52) ; also on sheet 8 12
LCD_DATA3: J2101.154(DM5) ; also on sheet 8 12
LCD_DATA4: J2101.158(DQ46) ; also on sheet 8 12
LCD_DATA5: J2101.149(DQ41) ; also on sheet 8 12
LCD_DATA6: J2101.151(GND18) ; also on sheet 8 12
LCD_DATA7: J2101.166(DQ53) ; also on sheet 8 12
LCD_DATA8: J2101.143(DQ35) ; also on sheet 8 12
LCD_DATA9: J2101.145(GND17) ; also on sheet 8 12
LCD_DATA10: J2101.152(GND47) ; also on sheet 8 12
LCD_DATA11: J2101.148(DQ44) ; also on sheet 8 12
LCD_DATA12: J2101.150(DQ45) ; also on sheet 8 12
LCD_DATA13: J2101.139(GND16) ; also on sheet 8 12
LCD_DATA14: J2101.141(DQ34) ; also on sheet 8 12
LCD_DATA15: J2101.142(DQ38) ; also on sheet 8 12
LCD_DATA16: J2101.144(DQ39) ; also on sheet 8 12
LCD_DATA17: J2101.133(DQ33) ; also on sheet 8 12
LCD_DATA18: J2101.137(DQS4) ; also on sheet 8 12
LCD_DATA19: J2101.138(DM4) ; also on sheet 8 12
LCD_DATA20: J2101.140(GND45) ; also on sheet 8 12
LCD_DATA21: J2101.129(DQ32) ; also on sheet 8 12
LCD_DATA22: J2101.131(GND15) ; also on sheet 8 12
LCD_DATA23: J2101.134(DQ37) ; also on sheet 8 12
LCD_DE: J2101.163(GND20) ; also on sheet 8 12
LCD_DISP: J2101.10(DM0) R2116.1 ; also on sheet 8
LCD_HSYNC: J2101.160(DQ47) ; also on sheet 8 12
LCD_nPWREN: U2101.7(Q7) ; also on sheet 8
LCD_PCLK: J2101.161(DQ43) ; also on sheet 8 12
LCD_RST: J2101.157(GND19) TP2128.1(Pin1)
LCD_VSYNC: J2101.162(GND49) ; also on sheet 8 12
MX6_POR_B: J2101.4(DQ4) SW2102.3(B1) SW2102.4(B2)
nUSB_OTG_CHD: J2101.31(GND5) TP2121.1(Pin1)
NVCC_CSI: C1824.1 C2101.1 C2102.1 J1802.4 J2101.196(SCL) Q1801.2(GATE) Q1802.2(GATE) R1806.1 R1807.1 R1810.1 R1819.1 R1820.1
ONOFF: J2101.14(DQ6) SW2101.3(B1) SW2101.4(B2) TP2116.1(TP)
PERI_PWREN: J2101.44(DM2) Q2101.1(GATE) R2101.1 R2109.1
PMIC_ON_REQ: J2101.5(GND1) TP2126.1(Pin1)
PMIC_STBY_REQ: J2101.3(DQ0) TP2127.1(Pin1)
POR_B: J2101.16(DQ7) ; also on sheet 16 18
SD1_CD: J2101.74(GND39) ; also on sheet 18
SD1_CLK: J2101.179(DQ51) ; also on sheet 18
SD1_CMD: J2101.173(DQS6) ; also on sheet 18
SD1_DATA0: J2101.167(DQ49) ; also on sheet 18
SD1_DATA1: J2101.171(~{DQS6}) ; also on sheet 18
SD1_DATA2: J2101.175(GND22) ; also on sheet 18
SD1_DATA3: J2101.169(GND21) ; also on sheet 18
SD1_nRST: J2101.56(DQ29) ; also on sheet 18
SHIFT_nOE: J2101.18(GND29) R2105.2 R2115.1 U2101.13(~{OE})
SHIFT_SDI: J2101.9(~{DQS0}) TP2110.1(TP) U2101.14(DS)
SHIFT_SHCP: J2101.7(DQ1) TP2111.1(TP) U2101.11(SHCP)
SHIFT_STCP: J2101.24(GND30) R2114.1 U2101.12(STCP)
SPDIF_TX: J2101.33(DQ10) ; also on sheet 12
UART1_RXD: J2101.63(~{DQS3}) TP2103.1(TP) ; also on sheet 16
UART1_TXD: J2101.57(DQ24) TP2102.1(TP) ; also on sheet 16
UART2_CTS_BB: J2101.69(DQ26) ; also on sheet 18
UART2_RTS_BB: J2101.73(GND12) ; also on sheet 18
UART2_RXD: J2101.67(GND11) ; also on sheet 18
UART2_TXD: J2101.65(DQS3) ; also on sheet 18
USB_HOST_VBUS: C2107.1 C2108.1 J2101.11(DQS0) ; also on sheet 17
USB_OTG1_DN: J2101.27(~{DQS1}) TP2107.1(TP) ; also on sheet 17
USB_OTG1_DP: J2101.25(GND4) TP2108.1(TP) ; also on sheet 17
USB_OTG1_ID: J2101.64(DQ30) ; also on sheet 17 18
USB_OTG1_OC: J2101.62(GND37) ; also on sheet 8 17 18
USB_OTG1_PWR: J2101.47(DQS2) ; also on sheet 8 15 17 18
USB_OTG1_VBUS: C2105.1 C2106.1 J2101.13(GND2) TP2109.1(TP) ; also on sheet 17
USB_OTG2_DN: J2101.21(DQ8) ; also on sheet 17
USB_OTG2_DP: J2101.19(GND3) ; also on sheet 17
USB_OTG2_OC: J2101.55(GND9) ; also on sheet 8 17 18
USB_OTG2_PWR: J2101.58(GND36) ; also on sheet 8 17 18
VCMSINK: J1801.6(P6) R1802.1
VENET_3V3: C1802.1 C1809.1 C1810.1 C1814.1 C1815.1 C2131.1 C2132.1 C2136.1 C2137.1 C2138.1 C2139.1 C2140.1 C2147.1 C2148.1 C2149.1 C2150.1 C2151.1 C2152.1 C2153.1 C2154.1 J1801.4(P4) Q2101.3(DRAIN) R1802.2 R2102.2 R2105.1 U1802.1(IN) U1802.3(~{SHDN}) U1803.1(IN) U1803.3(~{SHDN}) U2101.10(~{MR}) U2101.16(VCC) ; also on sheet 5 6 7 13 14 15 18
VSYS: C1801.1 C1805.1 J1802.1 J1802.2 L2101.2 L2102.2 TP2114.1(TP) ; also on sheet 5 8 15
N97210573: C1803.1 C1804.1 J1801.8(P8) L1801.1
N97210585: J1801.34(P34) R1805.1
N97210639: J1801.5(P5) R1801.2
N97210701: J1801.7(P7) R1803.2
N97210775: J1801.11(P11) R1804.2
N97708818: R1809.2 R1812.1 U1802.4(FB)
N97709332: R1813.2 R1816.1 U1803.4(FB)
N98020551: D1802.A J1801.17(P17) R1819.2
N98022424: D1801.A J1801.9(P9) R1820.2
N98627375: C2127.1 C2128.1 C2129.1 C2130.1 J2101.96(A11) J2101.98(VDD6) J2101.100(A8) J2101.102(A6) J2101.104(A4) J2101.106(VDD7) J2101.108(A1) J2101.110(A0) J2101.112(BA1) L2101.1 L2102.1

Not connected (* = marked no-connect by the designer): J1801 3(P3)* 10(P10) 12(P12)* 16(P16)* 18(P18)* 22(P22)* 24(P24)* 28(P28)* 30(P30)* 35(P35) 37(P37); J2101 83(DQS8) 86(CB2) 94(NC/A14) 95(A12) 125(NC/ODT1) 132(DQ36) 170(DM6) 174(DQ54) 176(DQ55) 182(DQ61); U2101 9(Q7S)

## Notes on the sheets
sheet 1
- i.MX6UL IOMUX
- NAME
- Default
- ALT0
- ALT1
- ALT2
- ALT3
- ALT4
- ALT5
- ALT6
- ALT7
- ALT8
- PAD DFU
- TEST_MODE
  POR_B
  ONOFF
  SNVS_PMIC_ON_REQ
  CCM_PMIC_STBY_REQ
  BOOT_MODE0
  BOOT_MODE1
  SNVS_TAMPER0
  SNVS_TAMPER1
  SNVS_TAMPER2
  SNVS_TAMPER3
  SNVS_TAMPER4
  SNVS_TAMPER5
  SNVS_TAMPER6
  SNVS_TAMPER7
  SNVS_TAMPER8
  SNVS_TAMPER9
  JTAG_MOD
  JTAG_TMS
  JTAG_TDO
  JTAG_TDI
  JTAG_TCK
  JTAG_TRST_B
  GPIO1_IO00
  GPIO1_IO01
  GPIO1_IO02
  GPIO1_IO03
  GPIO1_IO04
  GPIO1_IO05
  GPIO1_IO06
  GPIO1_IO07
  GPIO1_IO08
  GPIO1_IO09
  UART1_TXD
  UART1_RXD
  UART1_CTS
  UART1_RTS
  UART2_TXD
  UART2_RXD
  UART2_CTS
  UART2_RTS
  UART3_TXD
  UART3_RXD
  UART3_CTS
  UART3_RTS
  UART4_TXD
  UART4_RXD
  UART5_TXD
  UART5_RXD
  ENET1_RXD0
  ENET1_RXD1
  ENET1_CRS_DV
  ENET1_TXD0
  ENET1_TXD1
  ENET1_TXEN
  ENET1_TXCLK
  ENET1_RXER
  ENET2_RXD0
  ENET2_RXD1
  ENET2_CRS_DV
  ENET2_TXD0
  ENET2_TXD1
  ENET2_TXEN
  ENET2_TXCLK
  ENET2_RXER
  LCD_CLK
  LCD_ENABLE
  LCD_HSYNC
  LCD_VSYNC
  LCD_RESET
  LCD_DATA00
  LCD_DATA01
  LCD_DATA02
  LCD_DATA03
  LCD_DATA04
  LCD_DATA05
  LCD_DATA06
  LCD_DATA07
  LCD_DATA08
  LCD_DATA09
  LCD_DATA10
  LCD_DATA11
  LCD_DATA12
  LCD_DATA13
  LCD_DATA14
  LCD_DATA15
  LCD_DATA16
  LCD_DATA17
  LCD_DATA18
  LCD_DATA19
  LCD_DATA20
  LCD_DATA21
  LCD_DATA22
  LCD_DATA23
  NAND_RE_B
  NAND_WE_B
  NAND_DATA00
  NAND_DATA01
  NAND_DATA02
  NAND_DATA03
  NAND_DATA04
  NAND_DATA05
  NAND_DATA06
  NAND_DATA07
  NAND_ALE
  NAND_WP_B
  NAND_READY_B
  NAND_CE0_B
  NAND_CE1_B
  NAND_CLE
  NAND_DQS
  SD1_CMD
  SD1_CLK
  SD1_DATA0
  SD1_DATA1
  SD1_DATA2
  SD1_DATA3
  CSI_MCLK
  CSI_PIXCLK
  CSI_VSYNC
  CSI_HSYNC
  CSI_DATA00
  CSI_DATA01
  CSI_DATA02
  CSI_DATA03
  CSI_DATA04
  CSI_DATA05
  CSI_DATA06
  CSI_DATA07
- tcu.TEST_MODE
  src.POR_B
  src.RESET_B
  snvs_lp_wrapper.SNVS_WAKEUP_ALARM
  ccm.PMIC_VSTBY_REQ
  src.BOOT_MODE[0]
  src.BOOT_MODE[1]
  snvs_lp_wrapper.SNVS_TD1
  snvs_lp_wrapper.SNVS_TD1
  snvs_lp_wrapper.SNVS_TD1
  snvs_lp_wrapper.SNVS_TD1
  snvs_lp_wrapper.SNVS_TD1
  snvs_lp_wrapper.SNVS_TD1
  snvs_lp_wrapper.SNVS_TD1
  snvs_lp_wrapper.SNVS_TD1
  snvs_lp_wrapper.SNVS_TD1
  snvs_lp_wrapper.SNVS_TD1
  sjc.MOD
  sjc.TMS
  sjc.TDO
  sjc.TDI
  sjc.TCK
  sjc.TRSTB
  gpio1.IO[0]
  gpio1.IO[1]
  gpio1.IO[2]
  gpio1.IO[3]
  gpio1.IO[4]
  gpio1.IO[5]
  gpio1.IO[6]
  gpio1.IO[7]
  gpio1.IO[8]
  gpio1.IO[9]
  gpio1.IO[16]
  gpio1.IO[17]
  gpio1.IO[18]
  gpio1.IO[19]
  gpio1.IO[20]
  gpio1.IO[21]
  gpio1.IO[22]
  gpio1.IO[23]
  gpio1.IO[24]
  gpio1.IO[25]
  gpio1.IO[26]
  gpio1.IO[27]
  gpio1.IO[28]
  gpio1.IO[29]
  gpio1.IO[30]
  gpio1.IO[31]
  gpio2.IO[0]
  gpio2.IO[1]
  gpio2.IO[2]
  gpio2.IO[3]
  gpio2.IO[4]
  gpio2.IO[5]
  gpio2.IO[6]
  gpio2.IO[7]
  gpio2.IO[8]
  gpio2.IO[9]
  gpio2.IO[10]
  gpio2.IO[11]
  gpio2.IO[12]
  gpio2.IO[13]
  gpio2.IO[14]
  gpio2.IO[15]
  gpio3.IO[0]
  gpio3.IO[1]
  gpio3.IO[2]
  gpio3.IO[3]
  gpio3.IO[4]
  gpio3.IO[5]
  gpio3.IO[6]
  gpio3.IO[7]
  gpio3.IO[8]
  gpio3.IO[9]
  gpio3.IO[10]
  gpio3.IO[11]
  gpio3.IO[12]
  gpio3.IO[13]
  gpio3.IO[14]
  gpio3.IO[15]
  gpio3.IO[16]
  gpio3.IO[17]
  gpio3.IO[18]
  gpio3.IO[19]
  gpio3.IO[20]
  gpio3.IO[21]
  gpio3.IO[22]
  gpio3.IO[23]
  gpio3.IO[24]
  gpio3.IO[25]
  gpio3.IO[26]
  gpio3.IO[27]
  gpio3.IO[28]
  gpio4.IO[0]
  gpio4.IO[1]
  gpio4.IO[2]
  gpio4.IO[3]
  gpio4.IO[4]
  gpio4.IO[5]
  gpio4.IO[6]
  gpio4.IO[7]
  gpio4.IO[8]
  gpio4.IO[9]
  gpio4.IO[10]
  gpio4.IO[11]
  gpio4.IO[12]
  gpio4.IO[13]
  gpio4.IO[14]
  gpio4.IO[15]
  gpio4.IO[16]
  gpio2.IO[16]
  gpio2.IO[17]
  gpio2.IO[18]
  gpio2.IO[19]
  gpio2.IO[20]
  gpio2.IO[21]
  gpio4.IO[17]
  gpio4.IO[18]
  gpio4.IO[19]
  gpio4.IO[20]
  gpio4.IO[21]
  gpio4.IO[22]
  gpio4.IO[23]
  gpio4.IO[24]
  gpio4.IO[25]
  gpio4.IO[26]
  gpio4.IO[27]
  gpio4.IO[28]
- tcu.TEST_MODE
  src.POR_B
  src.RESET_B
  snvs_lp_wrapper.PMIC_ON_REQ
  ccm.PMIC_VSTBY_REQ
  src.BOOT_MODE[0]
  src.BOOT_MODE[1]
  snvs_lp_wrapper.TAMPER[0]
  snvs_lp_wrapper.TAMPER[1]
  snvs_lp_wrapper.TAMPER[2]
  snvs_lp_wrapper.TAMPER[3]
  snvs_lp_wrapper.TAMPER[4]
  snvs_lp_wrapper.TAMPER[5]
  snvs_lp_wrapper.TAMPER[6]
  snvs_lp_wrapper.TAMPER[7]
  snvs_lp_wrapper.TAMPER[8]
  snvs_lp_wrapper.TAMPER[9]
  sjc.MOD
  sjc.TMS
  sjc.TDO
  sjc.TDI
  sjc.TCK
  sjc.TRSTB
  i2c2.SCL
  i2c2.SDA
  i2c1.SCL
  i2c1.SDA
  anatop.ENET_REF_CLK1
  anatop.ENET_REF_CLK2
  enet1.MDIO
  enet1.MDC
  pwm1.OUT
  pwm2.OUT
  uart1.TX
  uart1.RX
  uart1.CTS_B
  uart1.RTS_B
  uart2.TX
  uart2.RX
  uart2.CTS_B
  uart2.RTS_B
  uart3.TX
  uart3.RX
  uart3.CTS_B
  uart3.RTS_B
  uart4.TX
  uart4.RX
  uart5.TX
  uart5.RX
  enet1.RDATA[0]
  enet1.RDATA[1]
  enet1.RX_EN
  enet1.TDATA[0]
  enet1.TDATA[1]
  enet1.TX_EN
  enet1.TX_CLK
  enet1.RX_ER
  enet2.RDATA[0]
  enet2.RDATA[1]
  enet2.RX_EN
  enet2.TDATA[0]
  enet2.TDATA[1]
  enet2.TX_EN
  enet2.TX_CLK
  enet2.RX_ER
  lcdif.CLK
  lcdif.ENABLE
  lcdif.HSYNC
  lcdif.VSYNC
  lcdif.RESET
  lcdif.DATA[0]
  lcdif.DATA[1]
  lcdif.DATA[2]
  lcdif.DATA[3]
  lcdif.DATA[4]
  lcdif.DATA[5]
  lcdif.DATA[6]
  lcdif.DATA[7]
  lcdif.DATA[8]
  lcdif.DATA[9]
  lcdif.DATA[10]
  lcdif.DATA[11]
  lcdif.DATA[12]
  lcdif.DATA[13]
  lcdif.DATA[14]
  lcdif.DATA[15]
  lcdif.DATA[16]
  lcdif.DATA[17]
  lcdif.DATA[18]
  lcdif.DATA[19]
  lcdif.DATA[20]
  lcdif.DATA[21]
  lcdif.DATA[22]
  lcdif.DATA[23]
  rawnand.RE_B
  rawnand.WE_B
  rawnand.DATA00
  rawnand.DATA01
  rawnand.DATA02
  rawnand.DATA03
  rawnand.DATA04
  rawnand.DATA05
  rawnand.DATA06
  rawnand.DATA07
  rawnand.ALE
  rawnand.WP_B
  rawnand.READY_B
  rawnand.CE0_B
  rawnand.CE1_B
  rawnand.CLE
  rawnand.DQS
  usdhc1.CMD
  usdhc1.CLK
  usdhc1.DATA0
  usdhc1.DATA1
  usdhc1.DATA2
  usdhc1.DATA3
  csi.MCLK
  csi.PIXCLK
  csi.VSYNC
  csi.HSYNC
  csi.DATA[2]
  csi.DATA[3]
  csi.DATA[4]
  csi.DATA[5]
  csi.DATA[6]
  csi.DATA[7]
  csi.DATA[8]
  csi.DATA[9]
- gpt2.CLK
  gpt2.CAPTURE1
  gpt2.CAPTURE2
  gpt2.COMPARE1
  gpt2.COMPARE2
  gpt2.COMPARE3
  gpt1.CAPTURE1
  gpt1.COMPARE1
  gpt1.COMPARE2
  gpt1.COMPARE3
  pwm3.OUT
  pwm4.OUT
  enet2.MDIO
  enet2.MDC
  wdog1.WDOG_B
  global wdog
  enet1.RDATA[2]
  enet1.RDATA[3]
  enet1.RX_CLK
  enet1.TX_ER
  enet1.TDATA[2]
  enet1.TDATA[3]
  enet1.CRS
  enet1.COL
  enet2.RDATA[2]
  enet2.RDATA[3]
  enet2.RX_CLK
  enet2.TX_ER
  enet2.TDATA[2]
  enet2.TDATA[3]
  enet2.CRS
  enet2.COL
  uart4.RTS_B
  uart4.CTS_B
  uart5.RTS_B
  uart5.CTS_B
  uart6.CTS_B
  uart6.RTS_B
  uart7.CTS_B
  uart7.RTS_B
  uart6.TX
  uart6.RX
  uart7.TX
  uart7.RX
  uart8.TX
  uart8.RX
  uart8.CTS_B
  uart8.RTS_B
  lcdif.WR_RWN
  lcdif.RD_E
  lcdif.RS
  lcdif.BUSY
  lcdif.CS
  pwm1.OUT
  pwm2.OUT
  pwm3.OUT
  pwm4.OUT
  uart8.CTS_B
  uart8.RTS_B
  uart7.CTS_B
  uart7.RTS_B
  spdif.IN
  sai3.MCLK
  sai3.RX_SYNC
  sai3.RX_BCLK
  sai3.TX_SYNC
  sai3.TX_BCLK
  sai3.RX_DATA
  sai3.TX_DATA
  uart7.TX
  uart7.RX
  pwm5.OUT
  pwm6.OUT
  uart8.TX
  uart8.RX
  mqs.RIGHT
  mqs.LEFT
  usdhc2.CLK
  usdhc2.CMD
  usdhc2.DATA0
  usdhc2.DATA1
  usdhc2.DATA2
  usdhc2.DATA3
  usdhc2.DATA4
  usdhc2.DATA5
  usdhc2.DATA6
  usdhc2.DATA7
  usdhc2.RESET_B
  usdhc1.RESET_B
  usdhc1.DATA4
  usdhc1.DATA5
  usdhc1.DATA6
  usdhc1.DATA7
  csi.FIELD
  gpt2.COMPARE1
  gpt2.COMPARE2
  gpt2.COMPARE3
  gpt2.CLK
  gpt2.CAPTURE1
  gpt2.CAPTURE2
  usdhc2.CD_B
  usdhc2.WP
  usdhc2.CLK
  usdhc2.CMD
  usdhc2.DATA0
  usdhc2.DATA1
  usdhc2.DATA2
  usdhc2.DATA3
  usdhc2.DATA4
  usdhc2.DATA5
  usdhc2.DATA6
  usdhc2.DATA7
- spdif.OUT
  sai2.MCLK
  sai2.TX_SYNC
  sai2.TX_BCLK
  sai2.RX_DATA
  sai2.TX_DATA
  anatop.OTG1_ID
  usb.OTG1_OC
  usb.OTG2_PWR
  usb.OTG2_OC
  usb.OTG1_PWR
  anatop.OTG2_ID
  usb.OTG_PWR_WAKE
  usb.OTG_HOST_MODE
  spdif.OUT
  spdif.IN
  i2c3.SCL
  i2c3.SDA
  usdhc1.WP
  usdhc1.CD_B
  i2c4.SCL
  i2c4.SDA
  can2.TX
  can2.RX
  sim1.PORT0_PD
  sim2.PORT0_PD
  can1.TX
  can1.RX
  i2c1.SCL
  i2c1.SDA
  i2c2.SCL
  i2c2.SDA
  pwm1.OUT
  pwm2.OUT
  osc32k.32K_OUT
  anatop.24M_OUT
  pwm5.OUT
  pwm6.OUT
  pwm7.OUT
  pwm8.OUT
  sim1.PORT0_TRXD
  sim1.PORT0_CLK
  sim1.PORT0_RST_B
  sim1.PORT0_SVEN
  sim2.PORT0_TRXD
  sim2.PORT0_CLK
  sim2.PORT0_RST_B
  sim2.PORT0_SVEN
  uart4.TX
  uart4.RX
  uart4.CTS_B
  uart4.RTS_B
  ca7_platform.EVENTI
  ca7_platform.TRACE[0]
  ca7_platform.TRACE[1]
  ca7_platform.TRACE[2]
  ca7_platform.TRACE[3]
  ca7_platform.TRACE[4]
  ca7_platform.TRACE[5]
  ca7_platform.TRACE[6]
  ca7_platform.TRACE[7]
  ca7_platform.TRACE[8]
  ca7_platform.TRACE[9]
  ca7_platform.TRACE[10]
  ca7_platform.TRACE[11]
  ca7_platform.TRACE[12]
  ca7_platform.TRACE[13]
  ca7_platform.TRACE[14]
  ca7_platform.TRACE[15]
  ca7_platform.TRACE_CLK
  ca7_platform.TRACE_CTL
  ca7_platform.EVENTO
  global wdog
  ecspi1.SCLK
  ecspi1.SS0
  ecspi1.MOSI
  ecspi1.MISO
  qspiB_SCLK
  qspiB_SS0_B
  qspiB_SS1_B
  qspiB_DQS
  qspiB_DATA[0]
  qspiB_DATA[1]
  qspiB_DATA[2]
  qspiB_DATA[3]
  sai2.RX_BCLK
  qspiA_SS1_B
  qspiA_DQS
  qspiA_SCLK
  qspiA_DATA[0]
  qspiA_DATA[1]
  qspiA_DATA[2]
  qspiA_DATA[3]
  qspiA_SS0_B
  sai2.RX_SYNC
  sai2.MCLK
  sai2.TX_SYNC
  sai2.TX_BCLK
  sai2.RX_DATA
  sai2.TX_DATA
  rawnand.CE2_B
  rawnand.CE3_B
  sim1.PORT1_CLK
  sim1.PORT1_PD
  sim1.PORT1_RST_B
  sim1.PORT1_SVEN
  sim1.PORT1_TRXD
  sim2.PORT1_PD
  sim2.PORT1_CLK
  sim2.PORT1_RST_B
  sim2.PORT1_SVEN
  sim2.PORT1_TRXD
- anatop.ENET_REF_CLK_25M
  ccm.CLKO1
  ccm.CLKO2
  ccm.OUT0
  ccm.OUT1
  ccm.OUT2
  anatop.ENET_REF_CLK1
  anatop.ENET_REF_CLK2
  anatop.ENET_REF_CLK_25M
  osc32k.32K_OUT
  anatop.24M_OUT
  csi.FIELD
  csi.MCLK
  csi.PIXCLK
  csi.VSYNC
  csi.HSYNC
  csi.DATA[2]
  csi.DATA[3]
  csi.DATA[4]
  csi.DATA[5]
  csi.DATA[6]
  csi.DATA[7]
  csi.DATA[8]
  csi.DATA[9]
  csi.DATA[1]
  csi.DATA[0]
  csi.DATA[10]
  csi.DATA[11]
  csi.DATA[12]
  csi.DATA[13]
  csi.DATA[14]
  csi.DATA[15]
  csi.DATA[16]
  csi.DATA[17]
  csi.DATA[18]
  csi.DATA[19]
  csi.DATA[20]
  csi.DATA[21]
  csi.DATA[22]
  csi.DATA[23]
  i2c3.SCL
  i2c3.SDA
  i2c4.SCL
  i2c4.SDA
  ecspi4.SCLK
  ecspi4.MOSI
  ecspi4.MISO
  ecspi4.SS0
  sai3.MCLK
  sai3.TX_SYNC
  sai3.TX_BCLK
  sai3.RX_DATA
  sai3.TX_DATA
  enet1.1588_EVENT2_IN
  enet1.1588_EVENT2_OUT
  enet1.1588_EVENT3_IN
  enet1.1588_EVENT3_OUT
  enet2.1588_EVENT2_IN
  enet2.1588_EVENT2_OUT
  enet2.1588_EVENT3_IN
  enet2.1588_EVENT3_OUT
  csi.DATA[16]
  csi.DATA[17]
  csi.DATA[18]
  csi.DATA[19]
  csi.DATA[20]
  csi.DATA[21]
  csi.DATA[22]
  csi.DATA[23]
  csi.DATA[1]
  csi.DATA[0]
  csi.DATA[10]
  csi.DATA[11]
  csi.DATA[12]
  csi.DATA[13]
  csi.DATA[14]
  csi.DATA[15]
  kpp.ROW[0]
  kpp.COL[0]
  kpp.ROW[1]
  kpp.COL[1]
  kpp.ROW[2]
  kpp.COL[2]
  ecspi4.SCLK
  ecspi4.MOSI
  ecspi4.MISO
  ecspi4.SS0
  pwm3.OUT
  pwm4.OUT
  ecspi3.SS0
  ecspi3.SCLK
  ecspi3.MOSI
  ecspi3.MISO
  pwm5.OUT
  spdif.OUT
  spdif.IN
  can1.TX
  can1.RX
  can2.TX
  can2.RX
  i2c1.SDA
  i2c1.SCL
  i2c2.SDA
  i2c2.SCL
  ecspi2.SCLK
  ecspi2.SS0
  ecspi2.MOSI
  ecspi2.MISO
  ecspi1.SCLK
  ecspi1.SS0
  ecspi1.MOSI
  ecspi1.MISO
- ccm.PMIC_RDY
  ccm.WAIT
  ccm.STOP
  pwm6.OUT
  pwm7.OUT
  pwm8.OUT
  mqs.RIGHT
  mqs.LEFT
  usdhc1.WP
  usdhc1.CD_B
  usdhc1.RESET_B
  usdhc1.VSELECT
  usdhc2.WP
  usdhc2.CD_B
  usdhc2.VSELECT
  usdhc2.RESET_B
  gpt1.COMPARE1
  gpt1.CLK
  enet2.1588_EVENT1_IN
  enet2.1588_EVENT1_OUT
  gpt1.CAPTURE1
  gpt1.CAPTURE2
  gpt1.COMPARE2
  gpt1.COMPARE3
  uart2.CTS_B
  uart2.RTS_B
  enet1.1588_EVENT1_IN
  enet1.1588_EVENT1_OUT
  csu.CSU_ALARM_AUT[2]
  csu.CSU_ALARM_AUT[1]
  csu.CSU_ALARM_AUT[0]
  csu.CSU_INT_DEB
  can1.TX
  can1.RX
  can2.TX
  can2.RX
  enet2.MDIO
  enet2.MDC
  anatop.ENET_REF_CLK1
  weim.CRE
  enet1.MDIO
  enet1.MDC
  weim.ADDR[26]
  weim.EB_B[2]
  weim.EB_B[3]
  weim.ACLK_FREERUN
  anatop.ENET_REF_CLK2
  weim.ADDR[25]
  weim.CS2_B
  weim.CS3_B
  wdog3.WDOG_RST_B_DEB
  wdog2.WDOG_B
  global wdog
  i2c3.SDA
  i2c3.SCL
  i2c4.SDA
  i2c4.SCL
  spdif.SR_CLK
  spdif.OUT
  spdif.LOCK
  spdif.EXT_CLK
  weim.DATA[0]
  weim.DATA[1]
  weim.DATA[2]
  weim.DATA[3]
  weim.DATA[4]
  weim.DATA[5]
  weim.DATA[6]
  weim.DATA[7]
  weim.DATA[8]
  weim.DATA[9]
  weim.DATA[10]
  weim.DATA[11]
  weim.DATA[12]
  weim.DATA[13]
  weim.DATA[14]
  weim.DATA[15]
  weim.EB_B[0]
  weim.EB_B[1]
  weim.AD[8]
  weim.AD[9]
  weim.AD[10]
  weim.AD[11]
  weim.AD[12]
  weim.AD[13]
  weim.AD[14]
  weim.AD[15]
  weim.ADDR[17]
  weim.BCLK
  weim.CS1_B
  weim.DTACK_B
  weim.ADDR[18]
  weim.ADDR[16]
  weim.WAIT
  weim.ADDR[19]
  weim.ADDR[20]
  weim.ADDR[21]
  weim.ADDR[22]
  weim.ADDR[23]
  weim.ADDR[24]
  weim.CS0_B
  weim.OE
  weim.RW
  weim.LBA_B
  weim.AD[0]
  weim.AD[1]
  weim.AD[2]
  weim.AD[3]
  weim.AD[4]
  weim.AD[5]
  weim.AD[6]
  weim.AD[7]
- gpio5.IO[10]
  gpio5.IO[11]
  gpio5.IO[0]
  gpio5.IO[1]
  gpio5.IO[2]
  gpio5.IO[3]
  gpio5.IO[4]
  gpio5.IO[5]
  gpio5.IO[6]
  gpio5.IO[7]
  gpio5.IO[8]
  gpio5.IO[9]
  gpio1.IO[10]
  gpio1.IO[11]
  gpio1.IO[12]
  gpio1.IO[13]
  gpio1.IO[14]
  gpio1.IO[15]
  gpio1.IO[0]
  gpio1.IO[1]
  gpio1.IO[2]
  gpio1.IO[3]
  gpio1.IO[4]
  gpio1.IO[5]
  gpio1.IO[6]
  gpio1.IO[7]
  gpio1.IO[8]
  gpio1.IO[9]
  gpio1.IO[16]
  gpio1.IO[17]
  gpio1.IO[18]
  gpio1.IO[19]
  gpio1.IO[20]
  gpio1.IO[21]
  gpio1.IO[22]
  gpio1.IO[23]
  gpio1.IO[24]
  gpio1.IO[25]
  gpio1.IO[26]
  gpio1.IO[27]
  gpio1.IO[28]
  gpio1.IO[29]
  gpio1.IO[30]
  gpio1.IO[31]
  gpio2.IO[0]
  gpio2.IO[1]
  gpio2.IO[2]
  gpio2.IO[3]
  gpio2.IO[4]
  gpio2.IO[5]
  gpio2.IO[6]
  gpio2.IO[7]
  gpio2.IO[8]
  gpio2.IO[9]
  gpio2.IO[10]
  gpio2.IO[11]
  gpio2.IO[12]
  gpio2.IO[13]
  gpio2.IO[14]
  gpio2.IO[15]
  gpio3.IO[0]
  gpio3.IO[1]
  gpio3.IO[2]
  gpio3.IO[3]
  gpio3.IO[4]
  gpio3.IO[5]
  gpio3.IO[6]
  gpio3.IO[7]
  gpio3.IO[8]
  gpio3.IO[9]
  gpio3.IO[10]
  gpio3.IO[11]
  gpio3.IO[12]
  gpio3.IO[13]
  gpio3.IO[14]
  gpio3.IO[15]
  gpio3.IO[16]
  gpio3.IO[17]
  gpio3.IO[18]
  gpio3.IO[19]
  gpio3.IO[20]
  gpio3.IO[21]
  gpio3.IO[22]
  gpio3.IO[23]
  gpio3.IO[24]
  gpio3.IO[25]
  gpio3.IO[26]
  gpio3.IO[27]
  gpio3.IO[28]
  gpio4.IO[0]
  gpio4.IO[1]
  gpio4.IO[2]
  gpio4.IO[3]
  gpio4.IO[4]
  gpio4.IO[5]
  gpio4.IO[6]
  gpio4.IO[7]
  gpio4.IO[8]
  gpio4.IO[9]
  gpio4.IO[10]
  gpio4.IO[11]
  gpio4.IO[12]
  gpio4.IO[13]
  gpio4.IO[14]
  gpio4.IO[15]
  gpio4.IO[16]
  gpio2.IO[16]
  gpio2.IO[17]
  gpio2.IO[18]
  gpio2.IO[19]
  gpio2.IO[20]
  gpio2.IO[21]
  gpio4.IO[17]
  gpio4.IO[18]
  gpio4.IO[19]
  gpio4.IO[20]
  gpio4.IO[21]
  gpio4.IO[22]
  gpio4.IO[23]
  gpio4.IO[24]
  gpio4.IO[25]
  gpio4.IO[26]
  gpio4.IO[27]
  gpio4.IO[28]
- sdma.EXT_EVENT[0]
  sdma.EXT_EVENT[1]
  mqs.RIGHT
  mqs.LEFT
  osc32k.32K_OUT
  anatop.24M_OUT
  enet1.1588_EVENT0_IN
  enet1.1588_EVENT0_OUT
  sdma.EXT_EVENT[0]
  ccm.DI0_EXT_CLK
  enet2.1588_EVENT0_IN
  enet2.1588_EVENT0_OUT
  ccm.WAIT
  ccm.STOP
  ccm.PMIC_RDY
  usdhc1.RESET_B
  anatop.USBPHY1_TSTI_TX_LS_MODE
  anatop.USBPHY1_TSTI_TX_HS_MODE
  anatop.USBPHY1_TSTI_TX_DN
  anatop.USBPHY1_TSTO_RX_SQUELCH
  anatop.USBPHY1_TSTO_RX_DISCON_DET
  anatop.USBPHY1_TSTO_RX_HS_RXD
  anatop.USBPHY2_TSTO_RX_FS_RXD
  anatop.USBPHY1_TSTO_RX_FS_RXD
  anatop.USBPHY1_TSTI_TX_DP
  anatop.USBPHY1_TSTI_TX_EN
  anatop.USBPHY1_TSTI_TX_HIZ
  anatop.USBPHY2_TSTO_RX_HS_RXD
  anatop.USBPHY1_TSTO_PLL_CLK20DIV
  anatop.USBPHY2_TSTO_PLL_CLK20DIV
  anatop.USBPHY2_TSTO_RX_SQUELCH
  anatop.USBPHY2_TSTO_RX_DISCON_DET
  kpp.ROW[0]
  kpp.COL[0]
  kpp.ROW[1]
  kpp.COL[1]
  kpp.ROW[2]
  kpp.COL[2]
  kpp.ROW[3]
  kpp.COL[3]
  kpp.ROW[4]
  kpp.COL[4]
  kpp.ROW[5]
  kpp.COL[5]
  kpp.ROW[6]
  kpp.COL[6]
  kpp.ROW[7]
  kpp.COL[7]
  ocotp_ctrl_wrapper.FUSE_LATCHED
  anatop.TESTI[0]
  anatop.TESTI[1]
  anatop.TESTI[2]
  anatop.TESTI[3]
  src.BT_CFG[0]
  src.BT_CFG[1]
  src.BT_CFG[2]
  src.BT_CFG[3]
  src.BT_CFG[4]
  src.BT_CFG[5]
  src.BT_CFG[6]
  src.BT_CFG[7]
  src.BT_CFG[8]
  src.BT_CFG[9]
  src.BT_CFG[10]
  src.BT_CFG[11]
  src.BT_CFG[12]
  src.BT_CFG[13]
  src.BT_CFG[14]
  src.BT_CFG[15]
  src.BT_CFG[24]
  src.BT_CFG[25]
  src.BT_CFG[26]
  src.BT_CFG[27]
  src.BT_CFG[28]
  src.BT_CFG[29]
  src.BT_CFG[30]
  src.BT_CFG[31]
  anatop.TESTO[0]
  anatop.TESTO[1]
  anatop.TESTO[2]
  anatop.TESTO[3]
  anatop.TESTO[4]
  anatop.TESTO[5]
  anatop.TESTO[6]
  anatop.TESTO[7]
  anatop.TESTO[8]
  anatop.TESTO[9]
  anatop.TESTO[10]
  anatop.TESTO[11]
  anatop.TESTO[12]
  anatop.TESTO[13]
  anatop.TESTO[14]
  anatop.TESTO[15]
  sdma.EXT_EVENT[1]
  sdma.EXT_EVENT[0]
  ccm.OUT0
  ccm.OUT1
  ccm.OUT2
  ccm.CLKO1
  ccm.CLKO2
  snvs_hp_wrapper.VIO_5_CTL
  snvs_hp_wrapper.VIO_5
  pwm7.OUT
  pwm8.OUT
  src.INT_BOOT
  sai1.MCLK
  sai1.RX_SYNC
  sai1.RX_BCLK
  sai1.TX_SYNC
  sai1.TX_BCLK
  sai1.RX_DATA
  sai1.TX_DATA
- src.SYSTEM_RESET
  src.EARLY_RESET
  src.ANY_PU_RESET
  src.TESTER_ACK
  ccm.PLL2_BYP
  ccm.PLL3_BYP
  ccm.REF_EN_B
  ecspi1.TESTER_TRIGGER
  ecspi2.TESTER_TRIGGER
  ecspi3.TESTER_TRIGGER
  ecspi4.TESTER_TRIGGER
  usdhc1.TESTER_TRIGGER
  usdhc2.TESTER_TRIGGER
  qspi.TESTER_TRIGGER
  rawnand.TESTER_TRIGGER
  sjc.DONE
  sjc.DE_B
  sjc.FAIL
  sjc.JTAG_ACT
  sim_m.HADDR[0]
  sim_m.HADDR[1]
  sim_m.HADDR[2]
  sim_m.HADDR[3]
  sim_m.HADDR[4]
  sim_m.HADDR[5]
  sim_m.HADDR[6]
  sim_m.HADDR[7]
  sim_m.HADDR[8]
  sim_m.HADDR[9]
  sim_m.HADDR[10]
  sim_m.HADDR[11]
  sim_m.HADDR[12]
  sim_m.HADDR[13]
  sim_m.HADDR[14]
  sim_m.HADDR[15]
  sim_m.HADDR[16]
  sim_m.HADDR[17]
  sim_m.HADDR[18]
  sim_m.HADDR[19]
  sim_m.HADDR[20]
  sim_m.HADDR[21]
  sim_m.HADDR[22]
  sim_m.HADDR[23]
  sim_m.HADDR[24]
  sim_m.HADDR[25]
  sim_m.HADDR[26]
  sim_m.HADDR[27]
  sim_m.HADDR[28]
  sim_m.HADDR[29]
  sim_m.HADDR[30]
  sim_m.HADDR[31]
  sim_m.HBURST[0]
  sim_m.HBURST[1]
  sim_m.HBURST[2]
  sim_m.HMASTLOCK
  sim_m.HPROT[0]
  sim_m.HPROT[1]
  sim_m.HPROT[2]
  sim_m.HPROT[3]
  sim_m.HREADYOUT
  sim_m.HRESP
  sim_m.HSIZE[0]
  sim_m.HSIZE[1]
  sim_m.HSIZE[2]
  sim_m.HWRITE
  tpsmp.CLK
  tpsmp.HDATA_DIR
  tpsmp.HTRANS[0]
  tpsmp.HTRANS[1]
  tpsmp.HDATA[0]
  tpsmp.HDATA[1]
  tpsmp.HDATA[2]
  tpsmp.HDATA[3]
  tpsmp.HDATA[4]
  tpsmp.HDATA[5]
  tpsmp.HDATA[6]
  tpsmp.HDATA[7]
  tpsmp.HDATA[8]
  tpsmp.HDATA[9]
  tpsmp.HDATA[10]
  tpsmp.HDATA[11]
  tpsmp.HDATA[12]
  tpsmp.HDATA[13]
  tpsmp.HDATA[14]
  tpsmp.HDATA[15]
  tpsmp.HDATA[16]
  tpsmp.HDATA[19]
  tpsmp.HDATA[17]
  tpsmp.HDATA[18]
  observe_mux.OUT[0]
  observe_mux.OUT[1]
  observe_mux.OUT[2]
  observe_mux.OUT[3]
  observe_mux.OUT[4]
  tpsmp.HDATA[20]
  tpsmp.HDATA[21]
  tpsmp.HDATA[22]
  tpsmp.HDATA[23]
  tpsmp.HDATA[24]
  tpsmp.HDATA[25]
  tpsmp.HDATA[26]
  tpsmp.HDATA[27]
  tpsmp.HDATA[28]
  tpsmp.HDATA[29]
  tpsmp.HDATA[30]
  tpsmp.HDATA[31]
- epit1.OUT
  epit2.OUT
  sim1.POWER_FAIL
  sim2.POWER_FAIL
  caam_wrapper.RNG_OSC_OBS
  wdog3.WDOG_B
  wdog1.WDOG_B
  uart1.TX
  uart1.RX
  uart5.TX
  uart5.RX
  uart1.CTS_B
  uart1.RTS_B
  uart5.RTS_B
  uart5.CTS_B
  spdif.OUT
  spdif.IN
  usdhc2.WP
  usdhc2.CD_B
  ecspi3.SS0
  ecspi3.SCLK
  ecspi3.MOSI
  ecspi3.MISO
  anatop.OTG1_ID
  epit1.OUT
  epit2.OUT
  wdog1.WDOG_B
  ecspi2.SCLK
  ecspi2.SS0
  ecspi2.MOSI
  ecspi2.MISO
  usdhc1.LCTL
  usdhc2.LCTL
  usdhc1.VSELECT
  usdhc2.VSELECT
  wdog1.WDOG_RST_B_DEB
  wdog2.WDOG_RST_B_DEB
  gpt1.CLK
  gpt1.CAPTURE2
  usb.OTG1_PWR
  usb.OTG1_OC
  anatop.ENET_REF_CLK_25M
  anatop.24M_OUT
  usb.OTG2_PWR
  usb.OTG2_OC
  anatop.OTG2_ID
  global wdog
  wdog1.WDOG_RST_B_DEB
  ecspi2.RDY
  ecspi2.SS1
  ecspi2.SS2
  ecspi2.SS3
  sai1.MCLK
  sai1.TX_SYNC
  sai1.TX_BCLK
  sai1.RX_DATA
  sai1.TX_DATA
  ecspi1.SS1
  ecspi1.SS2
  ecspi1.SS3
  can1.TX
  can1.RX
  can2.TX
  can2.RX
  ecspi1.RDY
  usdhc2.RESET_B
  usdhc2.DATA4
  usdhc2.DATA5
  usdhc2.DATA6
  usdhc2.DATA7
  usdhc2.CMD
  usdhc2.CLK
  usdhc2.DATA0
  usdhc2.DATA1
  usdhc2.DATA2
  usdhc2.DATA3
  ecspi3.SS2
  ecspi3.SS3
  ecspi4.RDY
  ecspi4.SS1
  ecspi4.SS2
  ecspi4.SS3
  uart2.TX
  uart2.RX
  uart2.CTS_B
  uart2.RTS_B
  ecspi3.SS1
  ecspi3.RDY
  uart3.TX
  uart3.RX
  uart3.CTS_B
  uart3.RTS_B
  spdif.EXT_CLK
  usb.OTG1_PWR
  usb.OTG1_OC
  anatop.OTG1_ID
  usb.OTG2_PWR
  usb.OTG2_OC
  anatop.OTG2_ID
  uart6.TX
  uart6.RX
  uart6.RTS_B
  uart6.CTS_B
  uart5.TX
  uart5.RX
  uart5.RTS_B
  uart5.CTS_B
  usdhc1.WP
  usdhc1.CD_B
  usdhc1.RESET_B
  usdhc1.VSELECT
- 100K PD
  100K PU
  100K PU
  100K PU
  100K PD
  100K PD
  100K PD
  Keeper
  Keeper
  Keeper
  Keeper
  Keeper
  Keeper
  Keeper
  Keeper
  Keeper
  Keeper
  100K PU
  47K PU
  100K PU
  47K PU
  47K PU
  47K PU
  Keeper
  Keeper
  Keeper
  Keeper
  Keeper
  Keeper
  Keeper
  Keeper
  Keeper
  Keeper
  Keeper
  Keeper
  Keeper
  Keeper
  Keeper
  Keeper
  Keeper
  Keeper
  Keeper
  Keeper
  Keeper
  Keeper
  Keeper
  Keeper
  Keeper
  Keeper
  Keeper
  Keeper
  Keeper
  Keeper
  Keeper
  Keeper
  Keeper
  Keeper
  Keeper
  Keeper
  Keeper
  Keeper
  Keeper
  Keeper
  Keeper
  Keeper
  Keeper
  Keeper
  Keeper
  Keeper
  Keeper
  Keeper
  Keeper
  Keeper
  Keeper
  Keeper
  Keeper
  Keeper
  Keeper
  Keeper
  Keeper
  Keeper
  Keeper
  Keeper
  Keeper
  Keeper
  Keeper
  Keeper
  Keeper
  Keeper
  Keeper
  Keeper
  Keeper
  Keeper
  Keeper
  Keeper
  Keeper
  Keeper
  Keeper
  Keeper
  Keeper
  Keeper
  Keeper
  Keeper
  Keeper
  Keeper
  Keeper
  Keeper
  Keeper
  Keeper
  Keeper
  Keeper
  Keeper
  Keeper
  Keeper
  Keeper
  Keeper
  Keeper
  Keeper
  Keeper
  Keeper
  Keeper
  Keeper
  Keeper
  Keeper
  Keeper
  Keeper
  Keeper
  Keeper
  Keeper
sheet 2
- NOTE:
- EMV SIM will be placed on the daughter board
- All pins using ~reset as harden :
- PAD
- Default State
- Simulation Value
- UART3_TX_DATA
- Output Buffer(LOW) during reset --> Output keeper + Input enable after reset done
- 0 in real silicon
- LCD_DATA00~LCD_DATA23
- 100K pull down + input enable during reset --> Output keeper + Input enable
  after reset done ( this is boot option, we don’t need change)
- 0 in real silicon
- PAD
- Default State
- Signal Path
- PAD Simulation Value
- UART3_TX_DATA
- Output Buffer(LOW) during reset --> Output keeper + Input enable after reset done
- sjc.ipt_jta_active --> PAD
- 0 in real silicon
- (note : sjc.ipt_jta_active
  also connected to
  snvs_hp.sec_vio_in_1.
  This is security related,
  we don’t plan to
  change it.)
- ALT7
- All pins using ~src.en_system_clk as harden :
- PAD
- Default State
- Simulation Value
- GPIO1_IO03
- 100K pull down + input enable during reset --> Output keeper + Input enable
  after reset done
- 0 in real silicon
- PAD
- Default State
- Signal Path
- PAD Simulation Value
- GPIO1_IO03
- 100K pull down + input enable during reset --> Output keeper + Input enable after
  reset done
- PAD --> ccmsrcmix. src_tester_ack
- 0 in real silicon
- This is the requirement of TE test
- ALT7
- All pins using snvs_hp.snvs_sec_vio_in_5_en as harden :
- PAD
- Default State
- Simulation Value
- CSI_PIXCLK
- Output keeper + Input enable (snvs_sec_vio_in_5_en is 1’b0 in normal state,
  so harden is not triggerd in normal state). snvs_sec_vio_in_5_en is controlled
  by SNVS register. It can be disable or enable.
- X (0 or 1 in real silicon )
sheet 3
- TP for SODIMM MFG
- SODIMM 200
- CPU SODIMM TST/DBG
- # Camera/EVMSIM
- # SD CARD
- BMOD TP for MFG TOOL
- # LCD/HDMI
- PHY PWR
- # LCD_RST has been used as WDOG on CPU BOARD
- # 100M RMII PHY
- Reduce the VSNVS Power consumption during power down mode
- # Maxim DCDC_3V3 supply
  current for Base Board: 1.2A
- # VDD_SNVS_IN PWR Domain
- # BT UART
- # Debug UART
- # JTAG/Audio
- # CPU ONOFF Button
- # USB OTG
- # USB HOST
- # System Reset Button
sheet 4
- Camera / SIM
- Use Omnivision OV5640/5642 5M Pixel
  Sensor with this connector (not
  included)
- CMOS SENSOR
- OV5640 5MP
- AVDD is 2.6-3.1V of sensor analog power (clean).
- DOVDD is 1.7~3.1V of sensor digital IO power (clean). 1.8V is recommended.
- DVDD is 1.5V of sensor core power (clean).
- # 3.3V -- 1.8V
- CMOS_AVDD
- CMOS_MCLK
- CMOS_DVDD
- CMOS DOVDD
- 1.5V PWR
- Vfb=1V
- # 1.5V: R1/R2 = 0.7/0.8 : 140K/160K
- # fdv301n
- RSV for SIM
- 2.8V PWR
- Vfb=1V
- # 2.8V: R1/R2 = 2/0.8 : 400K/160K
